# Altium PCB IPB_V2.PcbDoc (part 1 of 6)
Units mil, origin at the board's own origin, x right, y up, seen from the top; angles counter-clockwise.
Board outline 14000 x 12000 mil, 6 copper layers (Top, L2 - Plane/Horiz, L3 - Horiz, L4 - Vert, L5 - Plane/Horiz, Bottom), stack 61.468 mil thick; 657 components, 436 nets, 1897 pads, 873 vias.
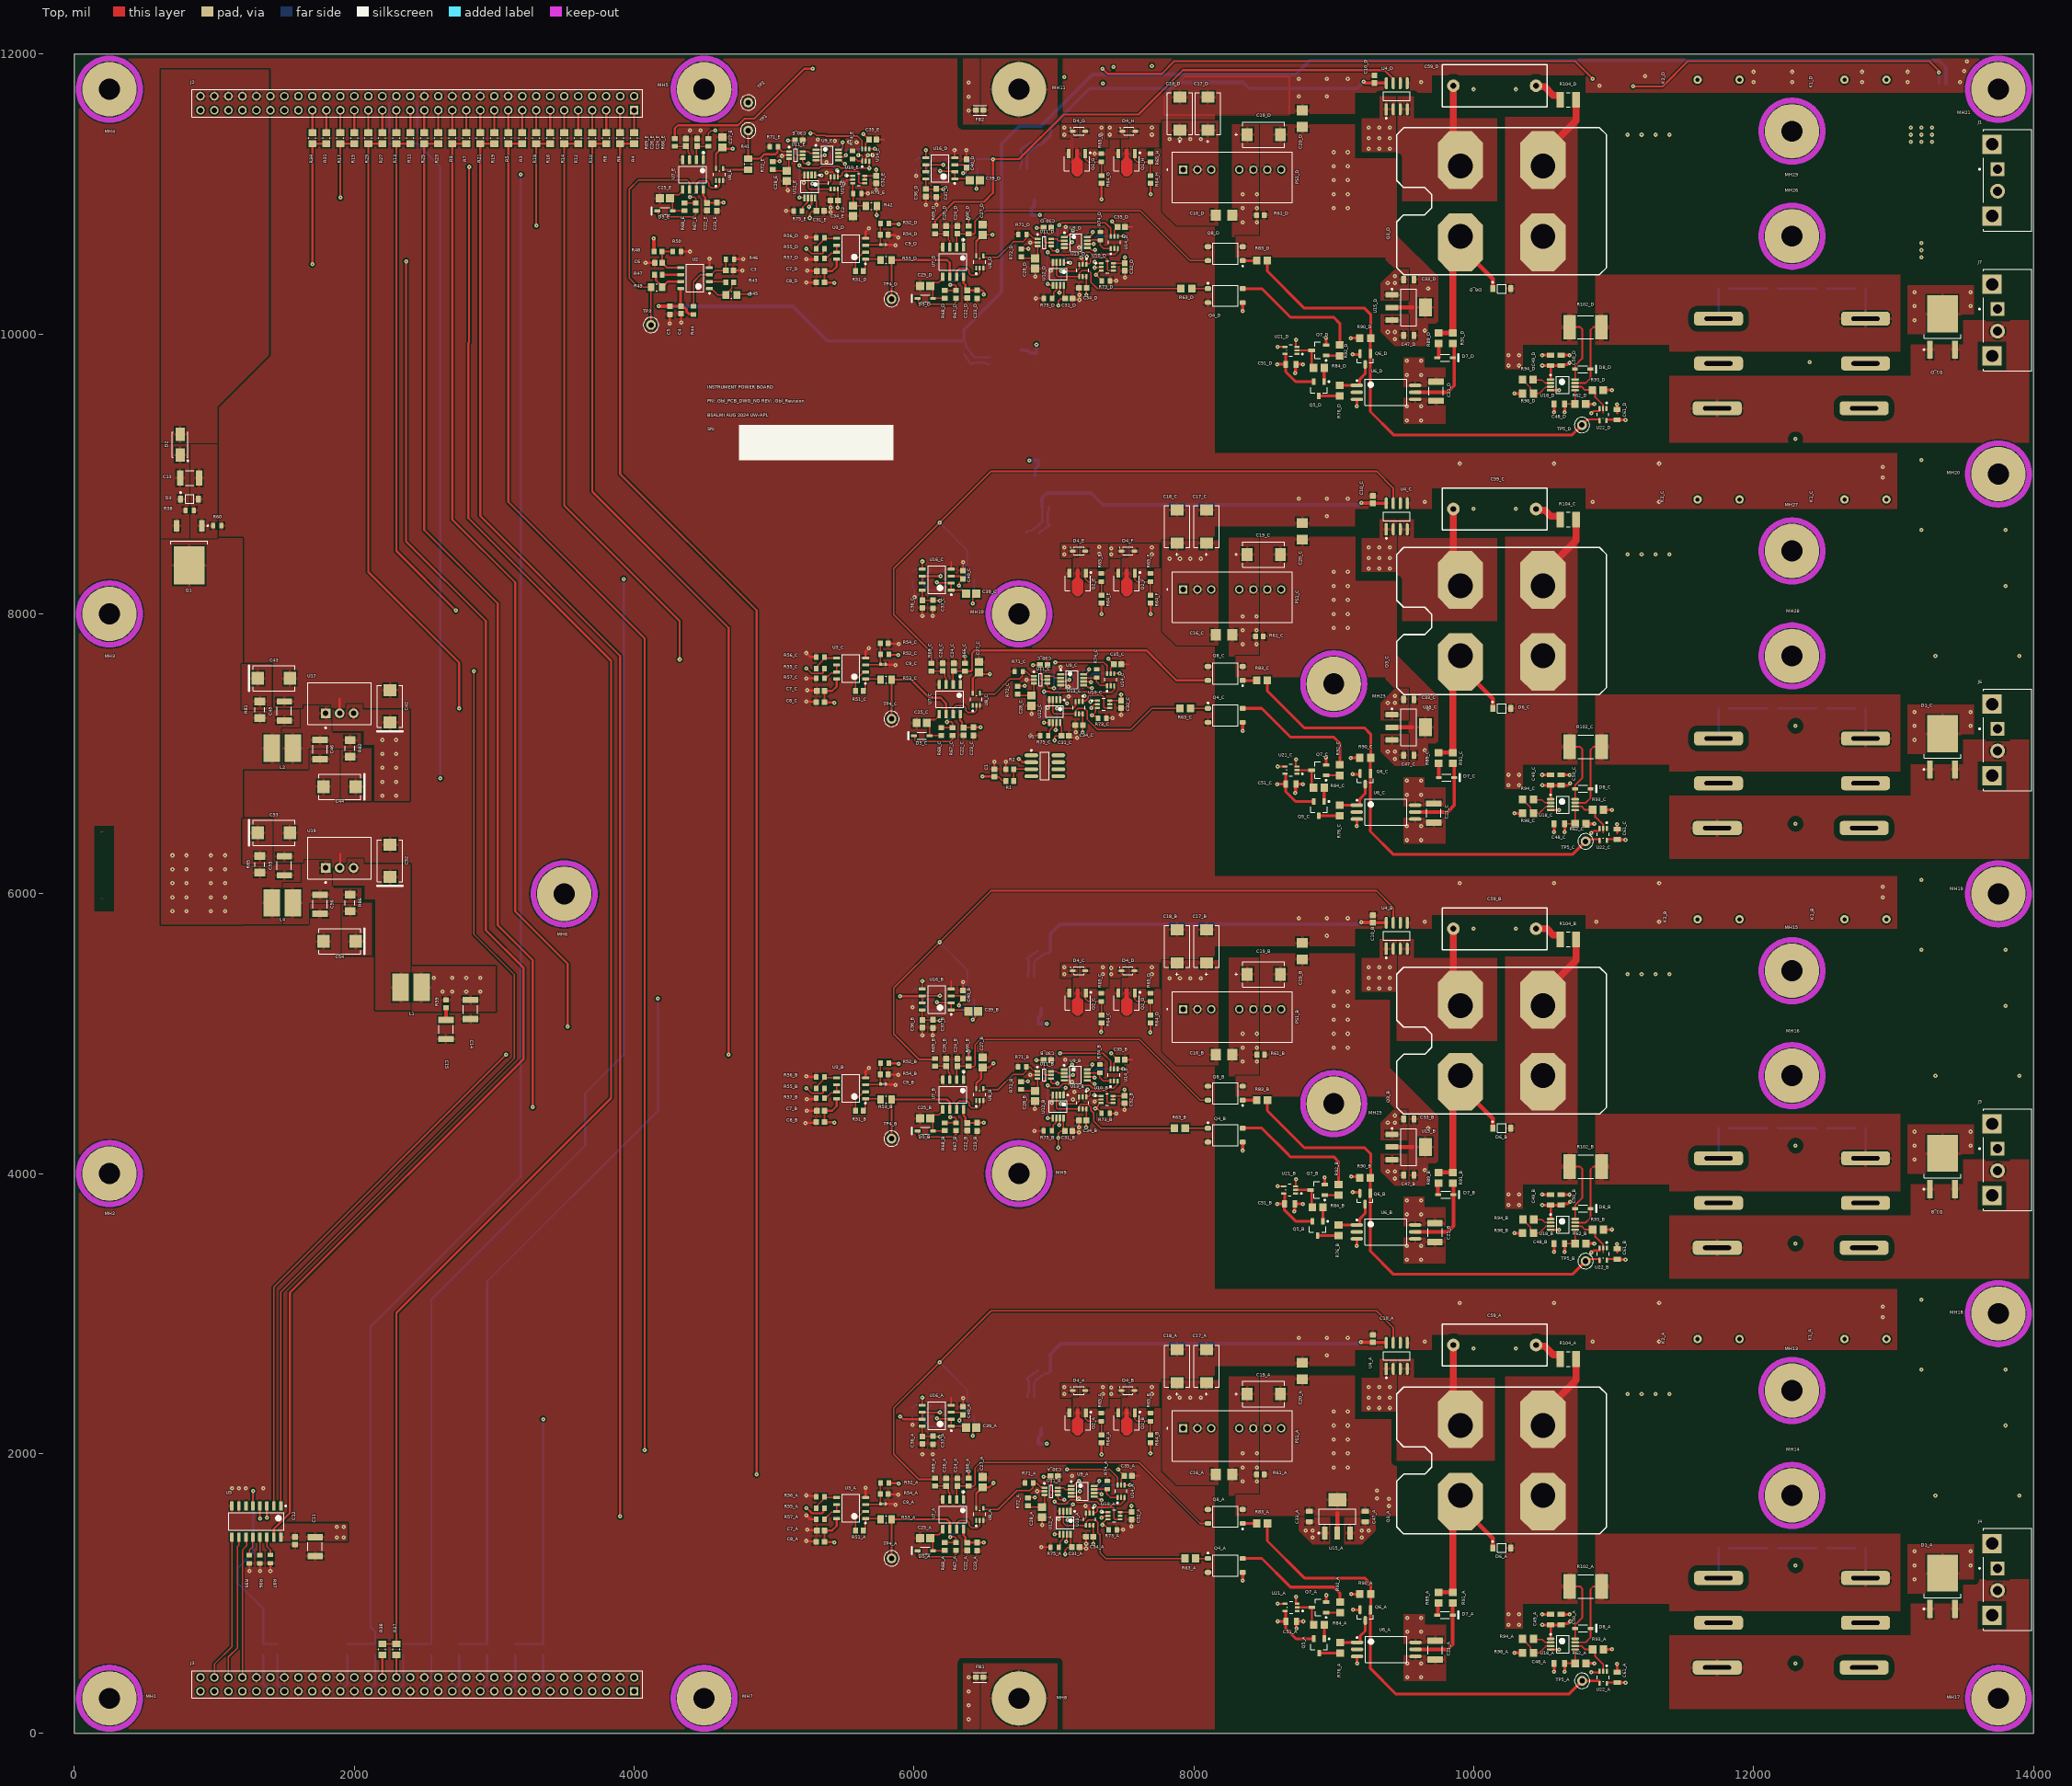
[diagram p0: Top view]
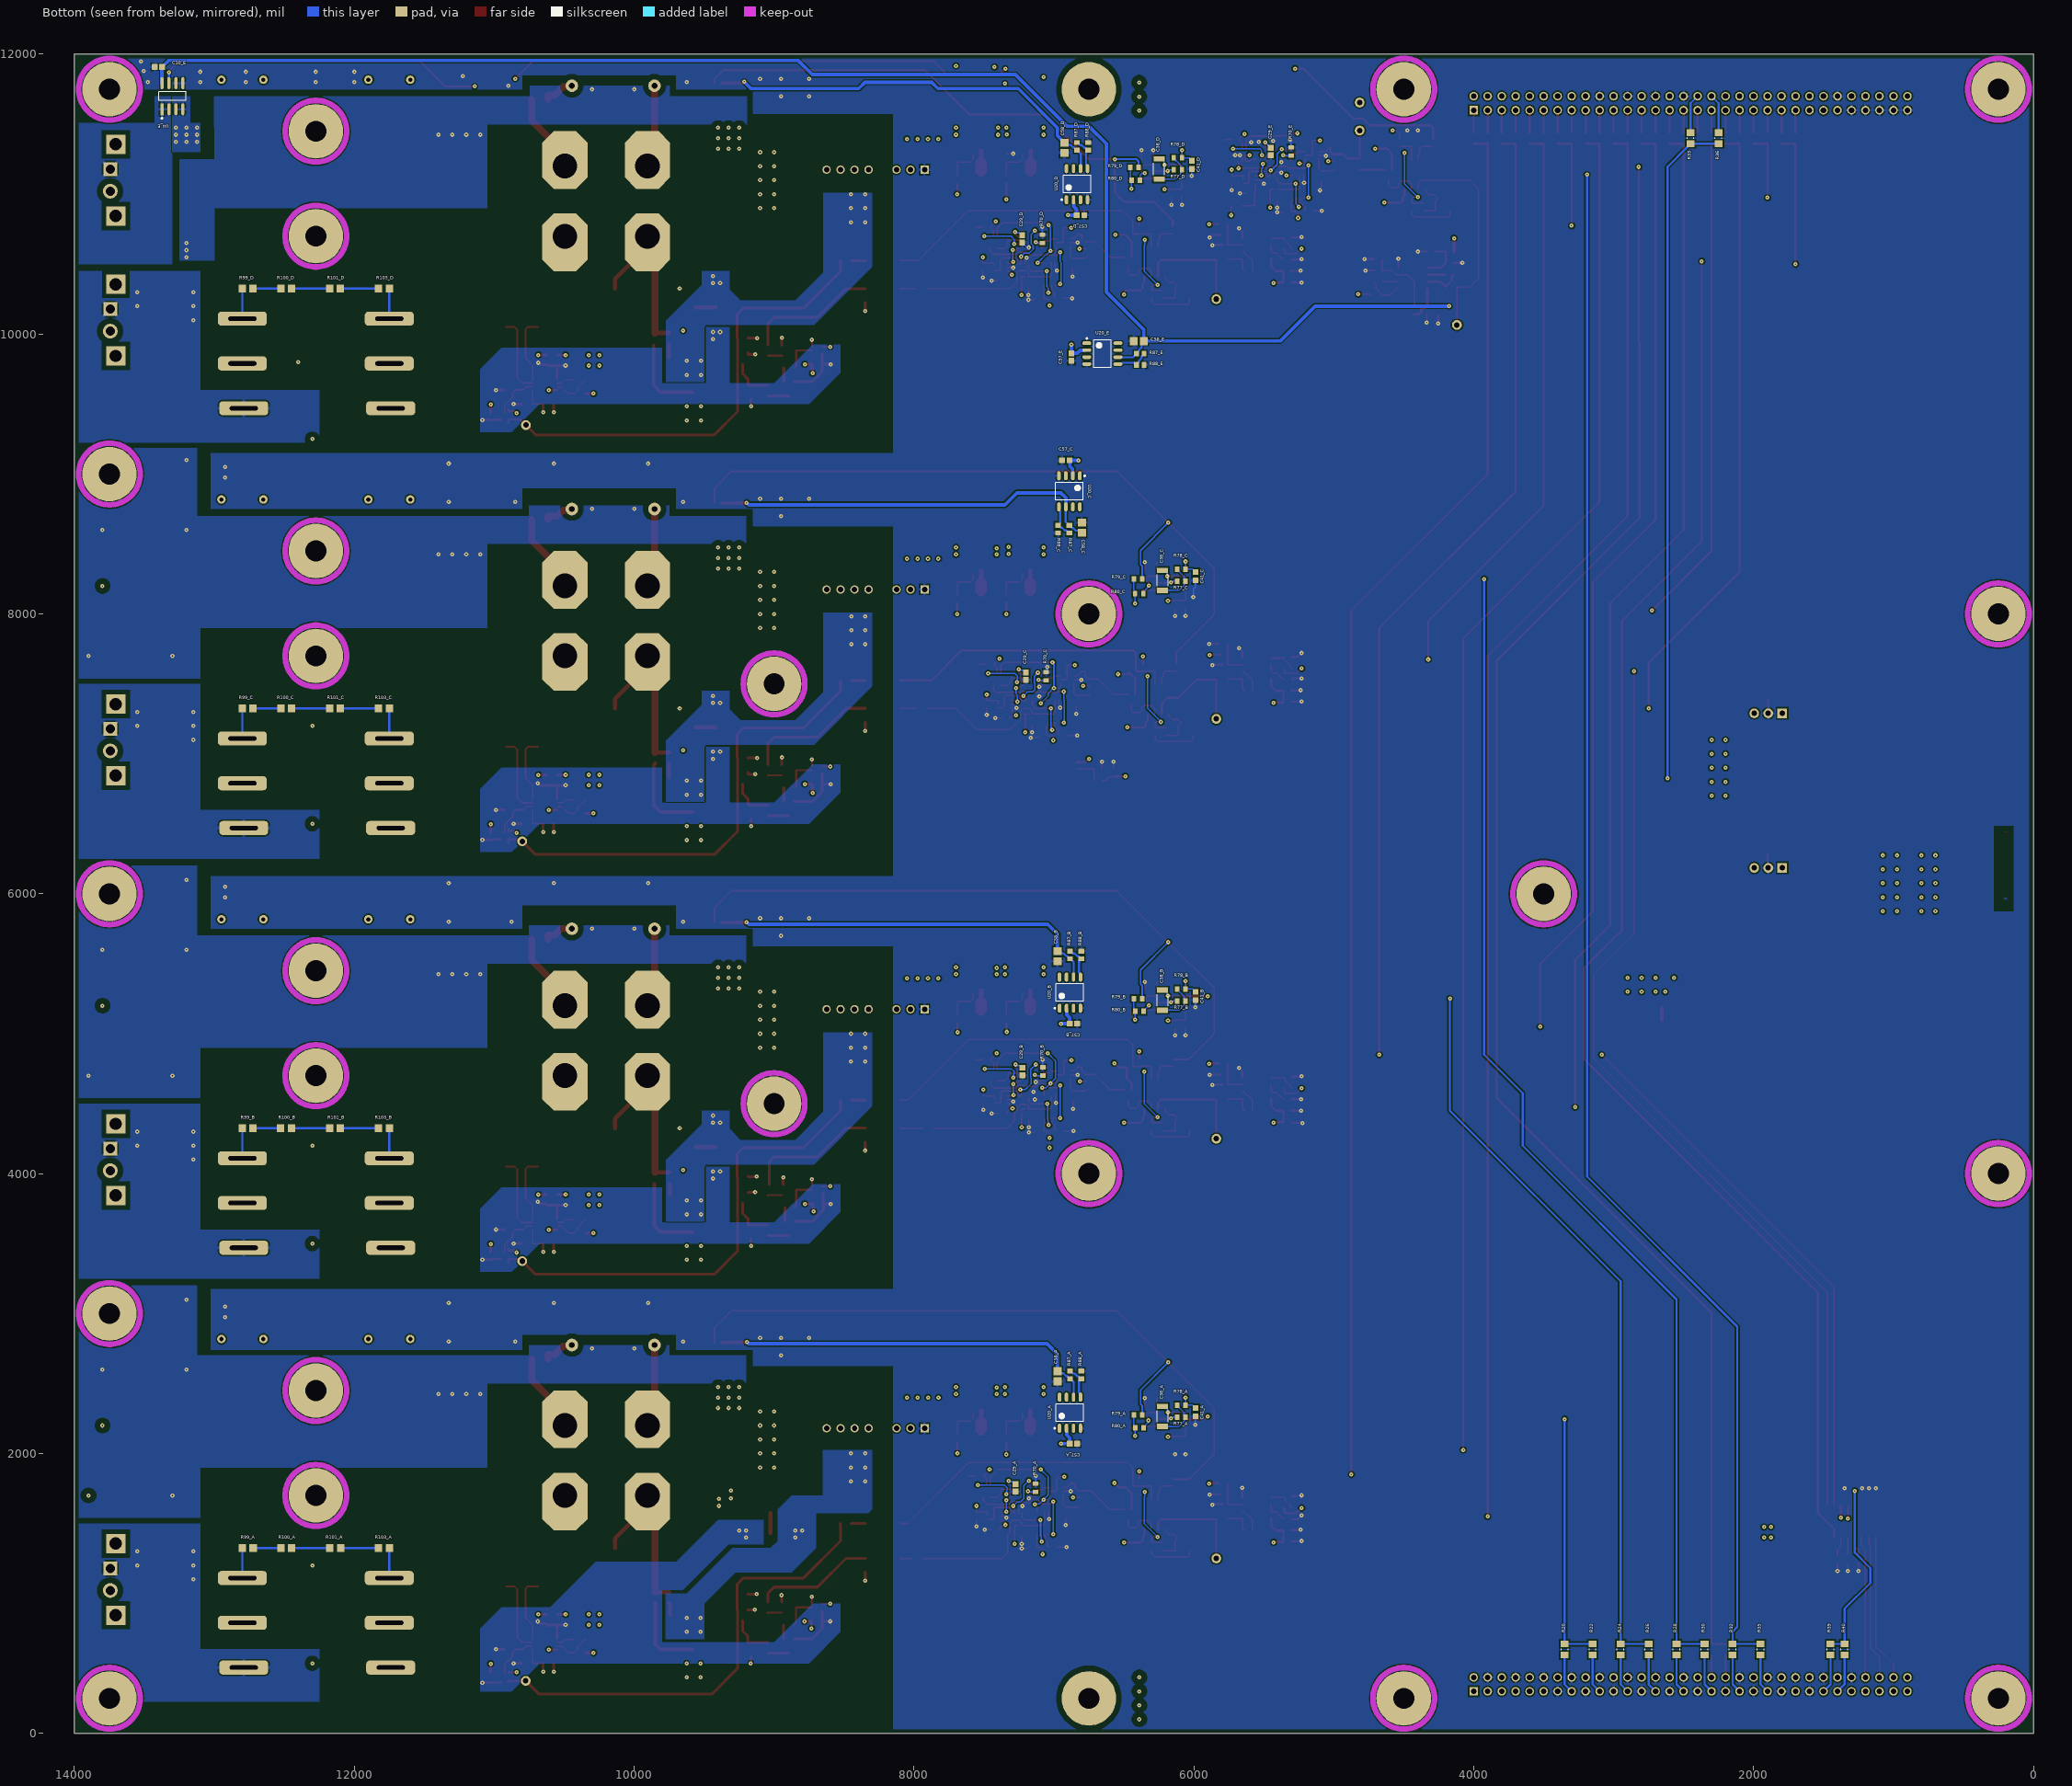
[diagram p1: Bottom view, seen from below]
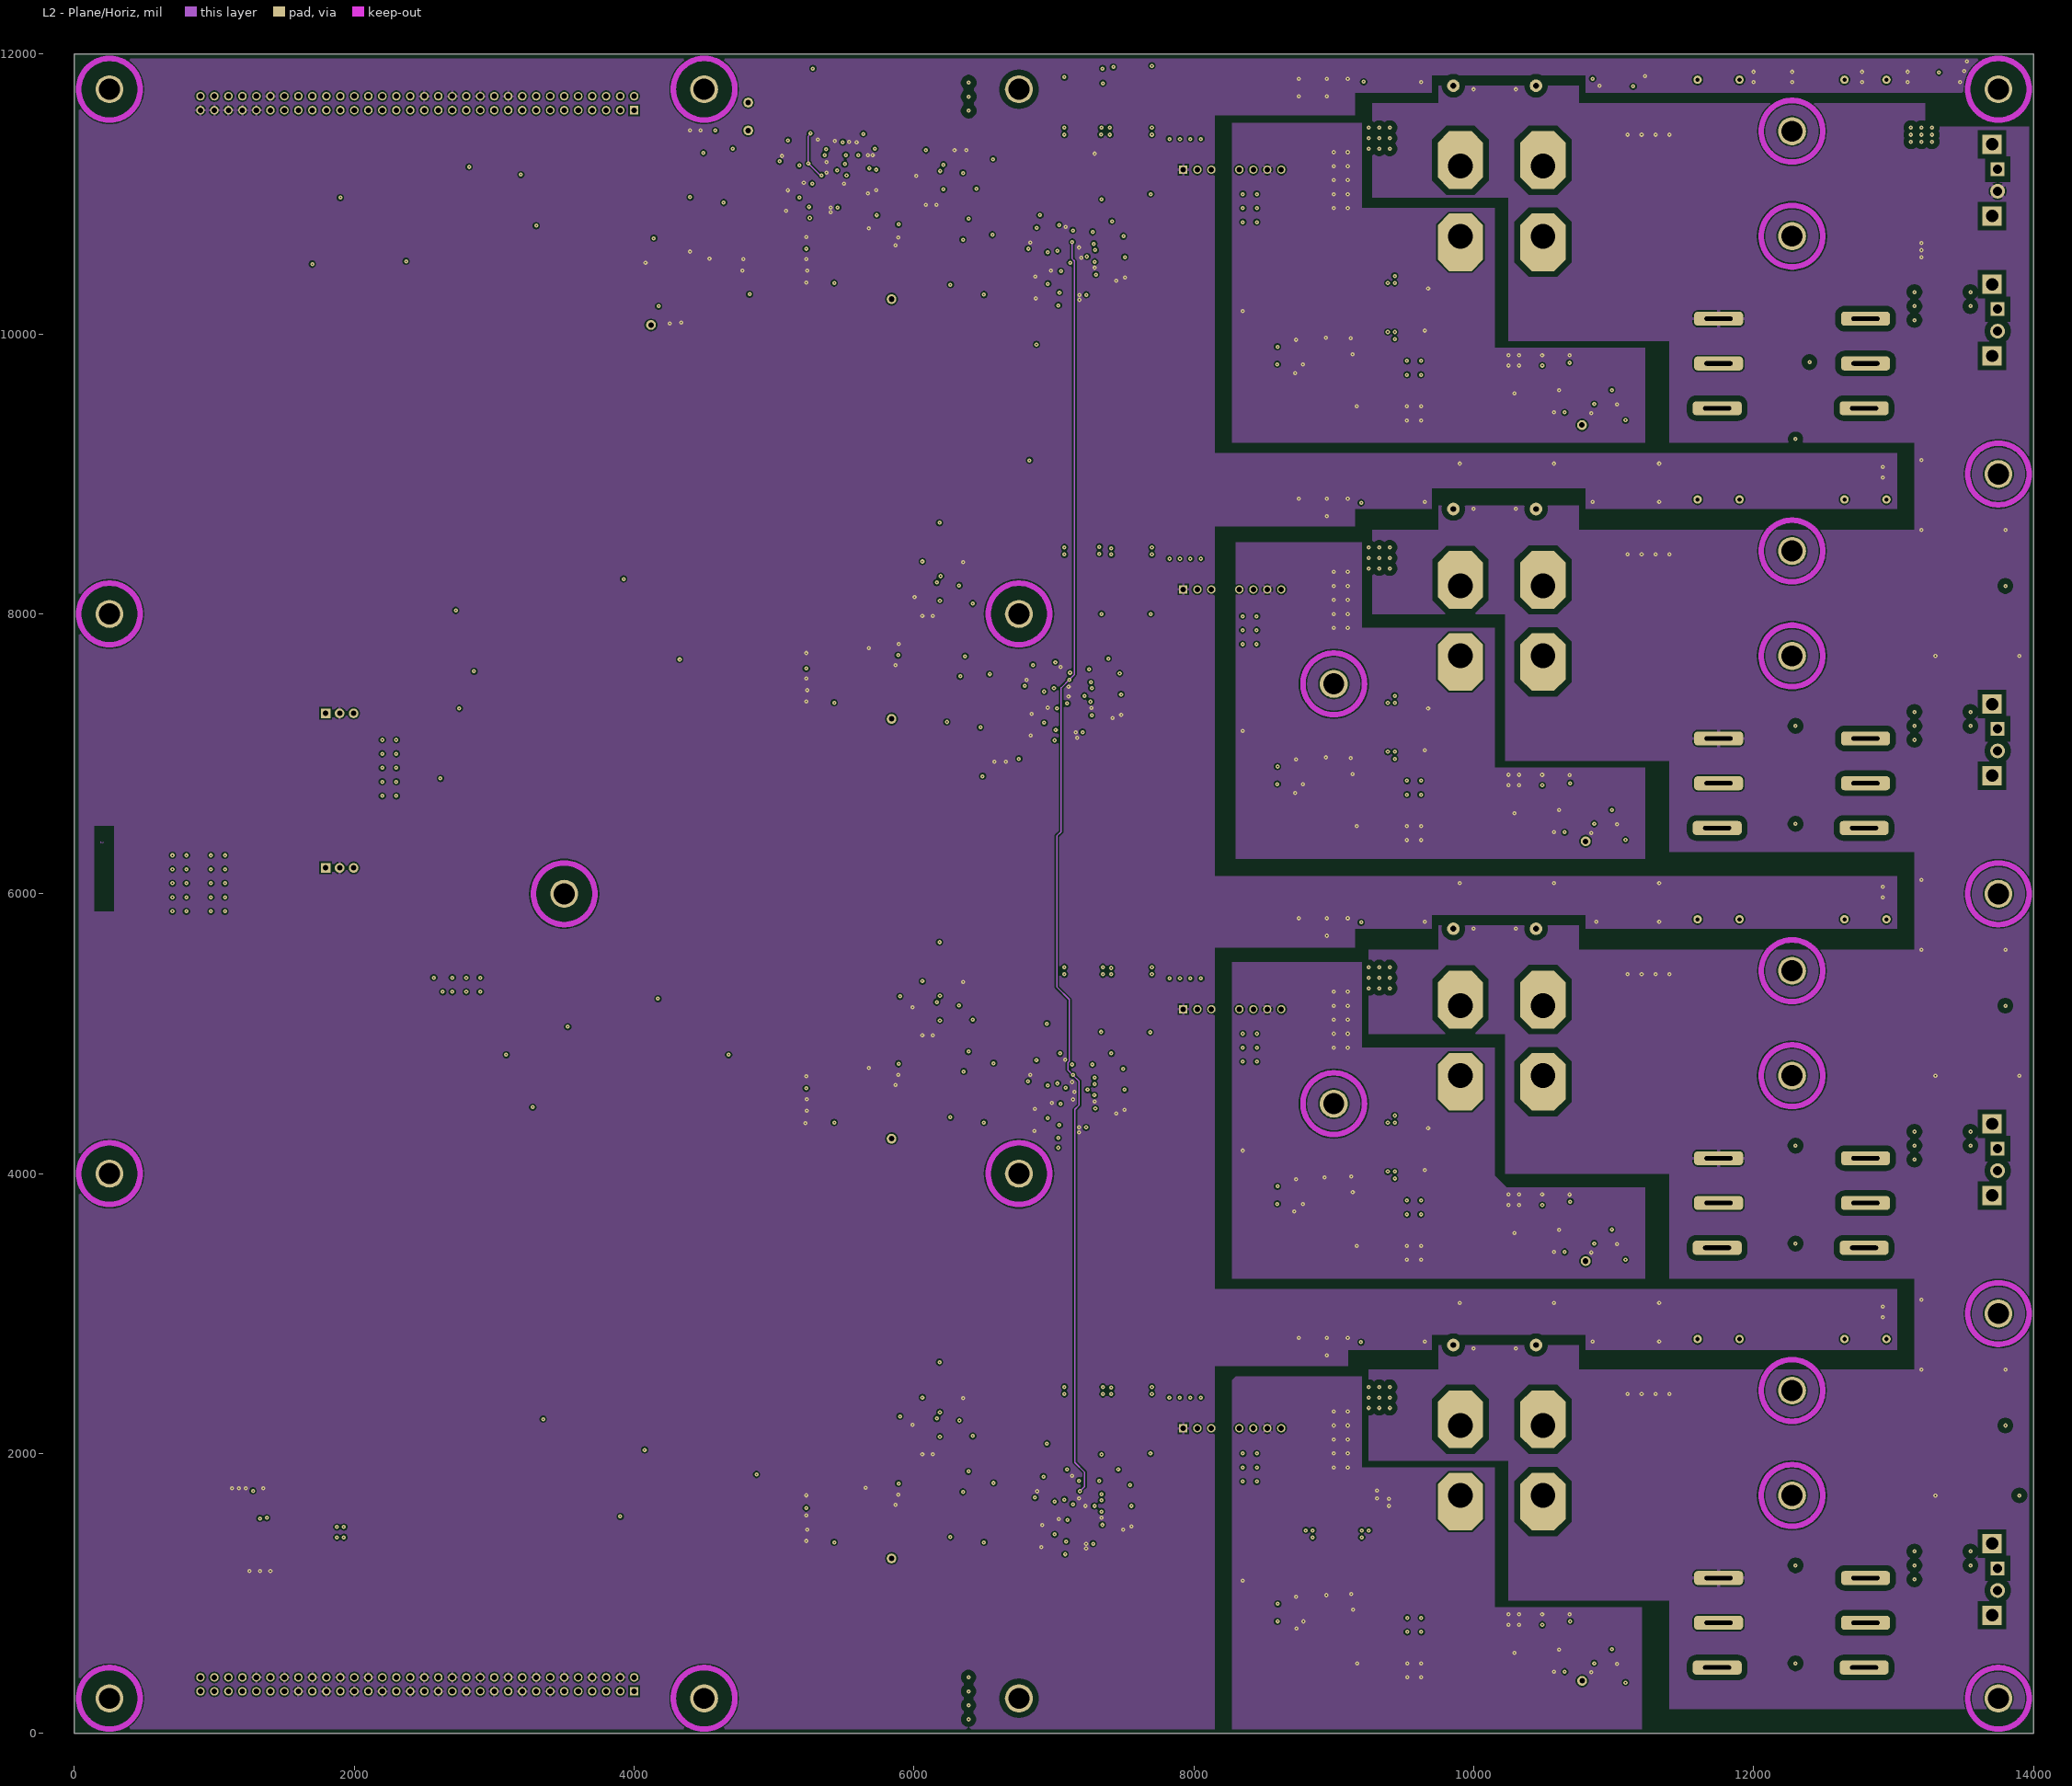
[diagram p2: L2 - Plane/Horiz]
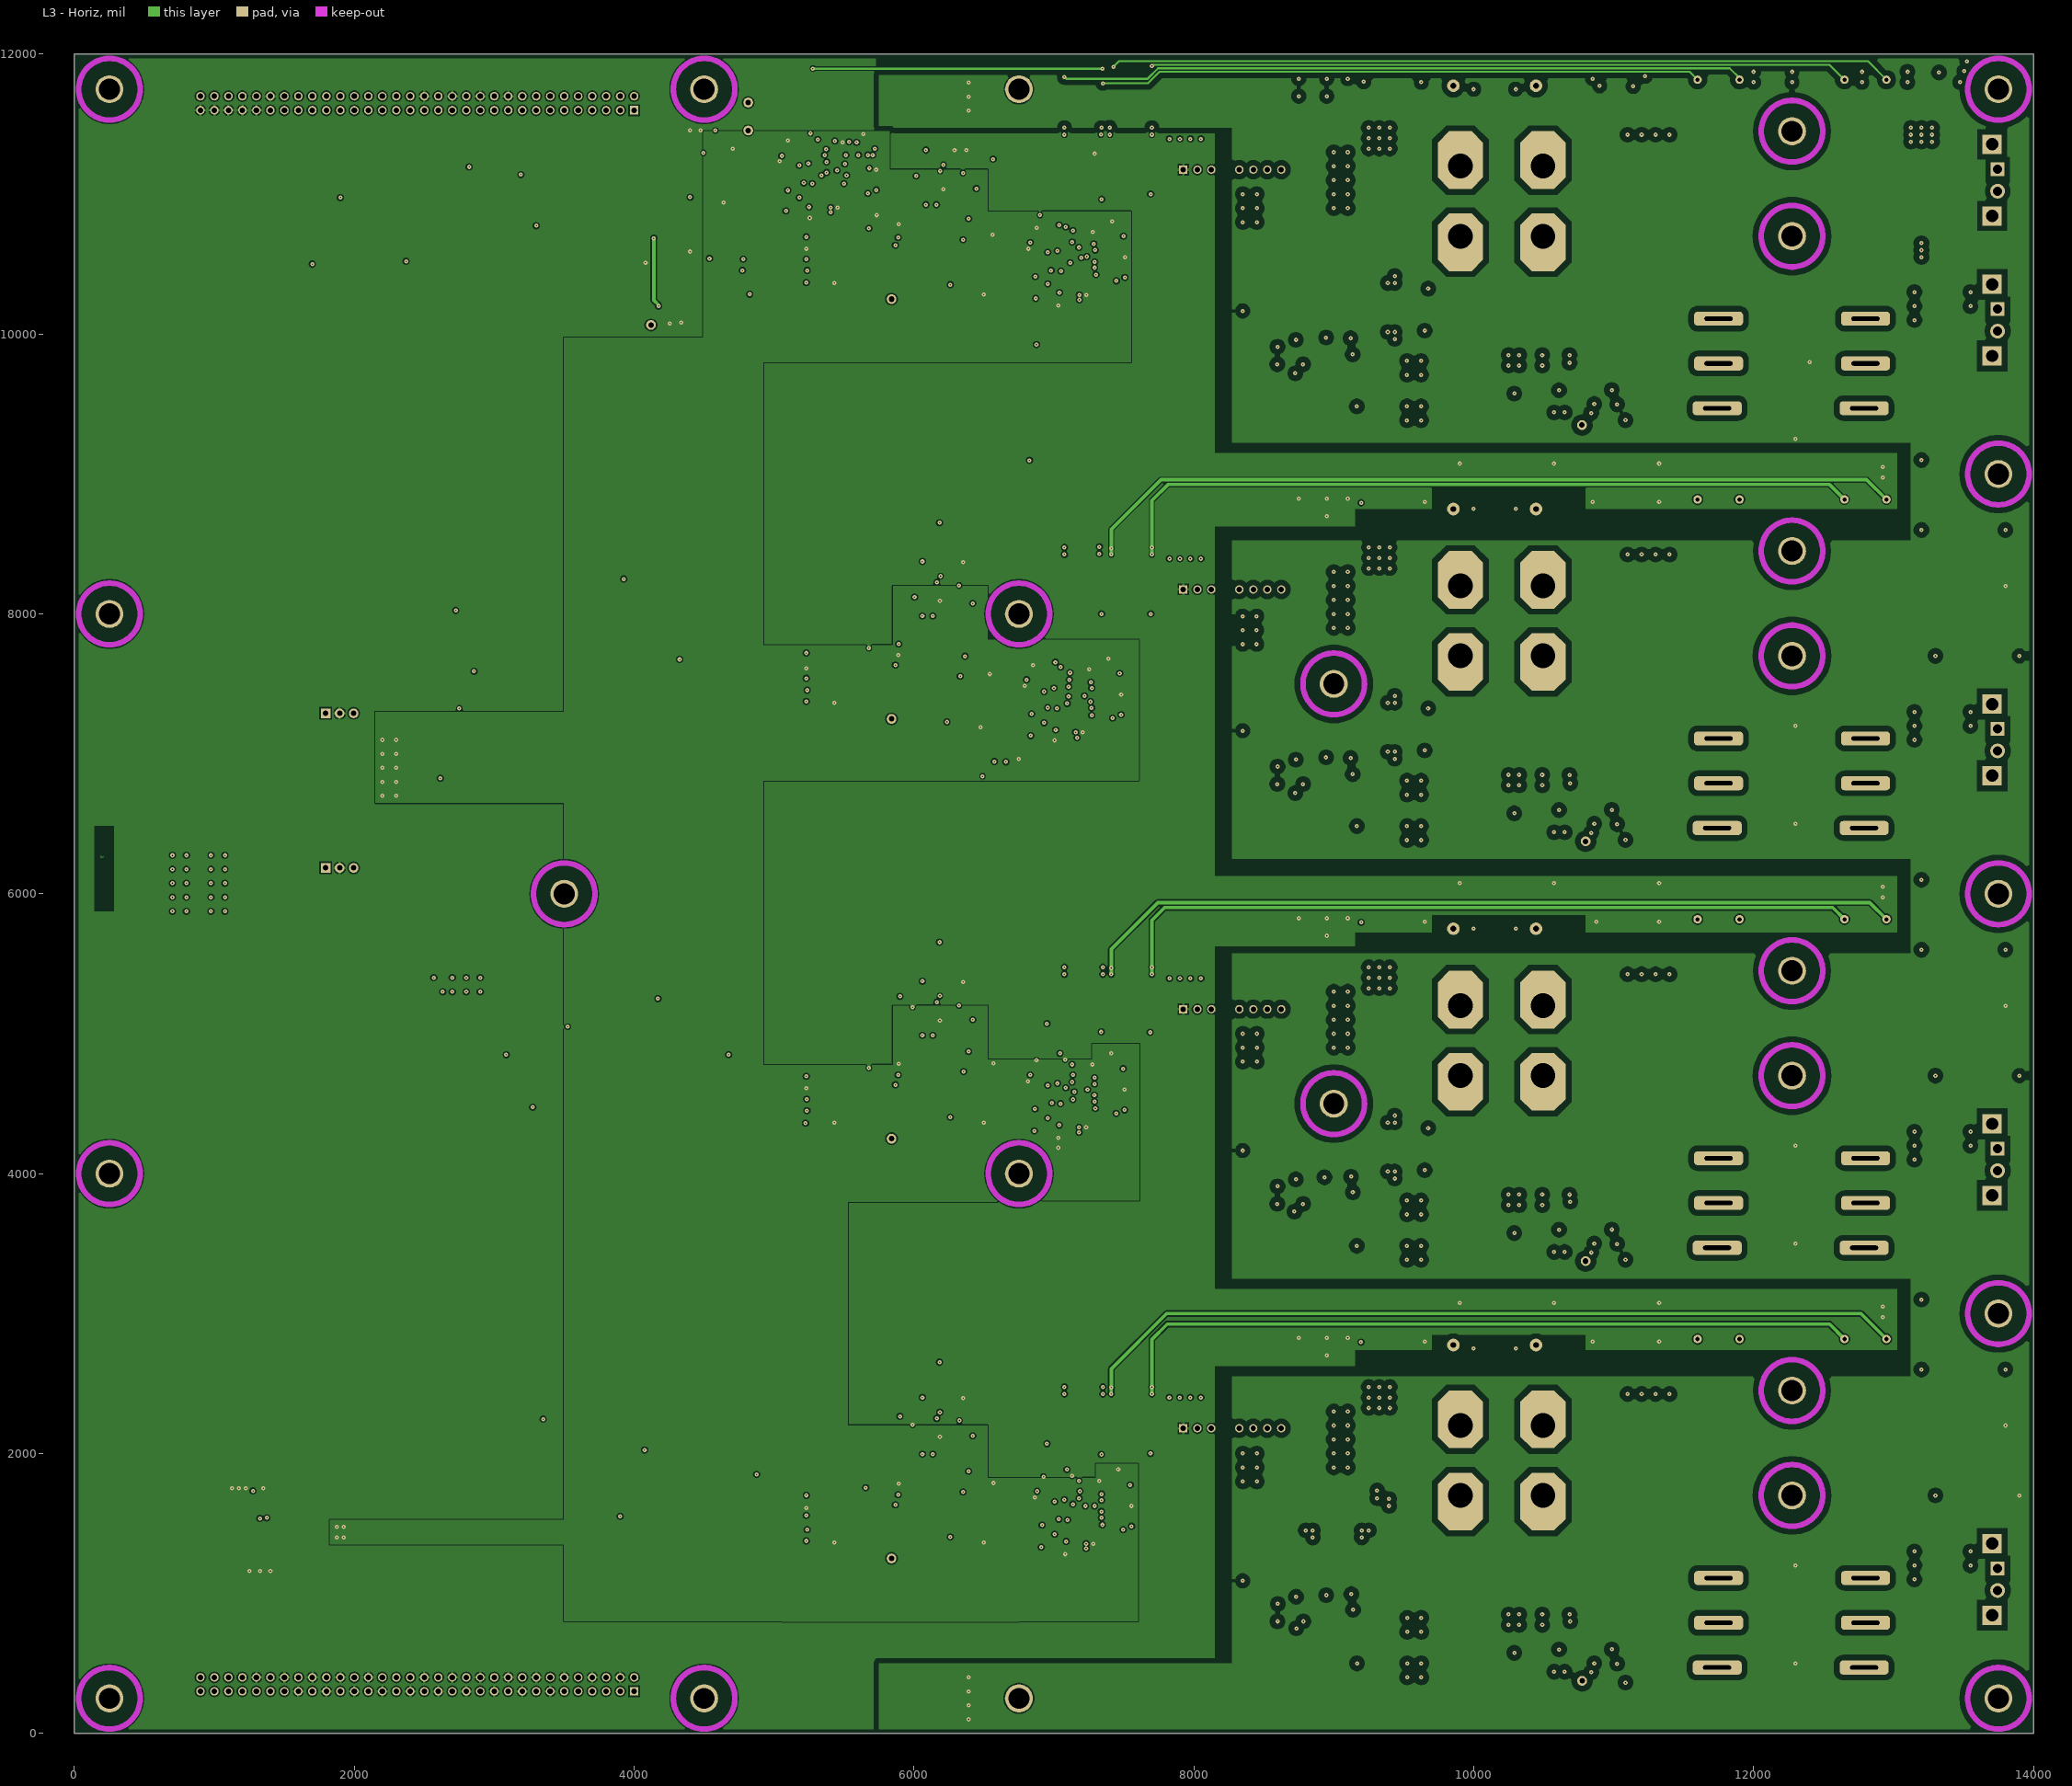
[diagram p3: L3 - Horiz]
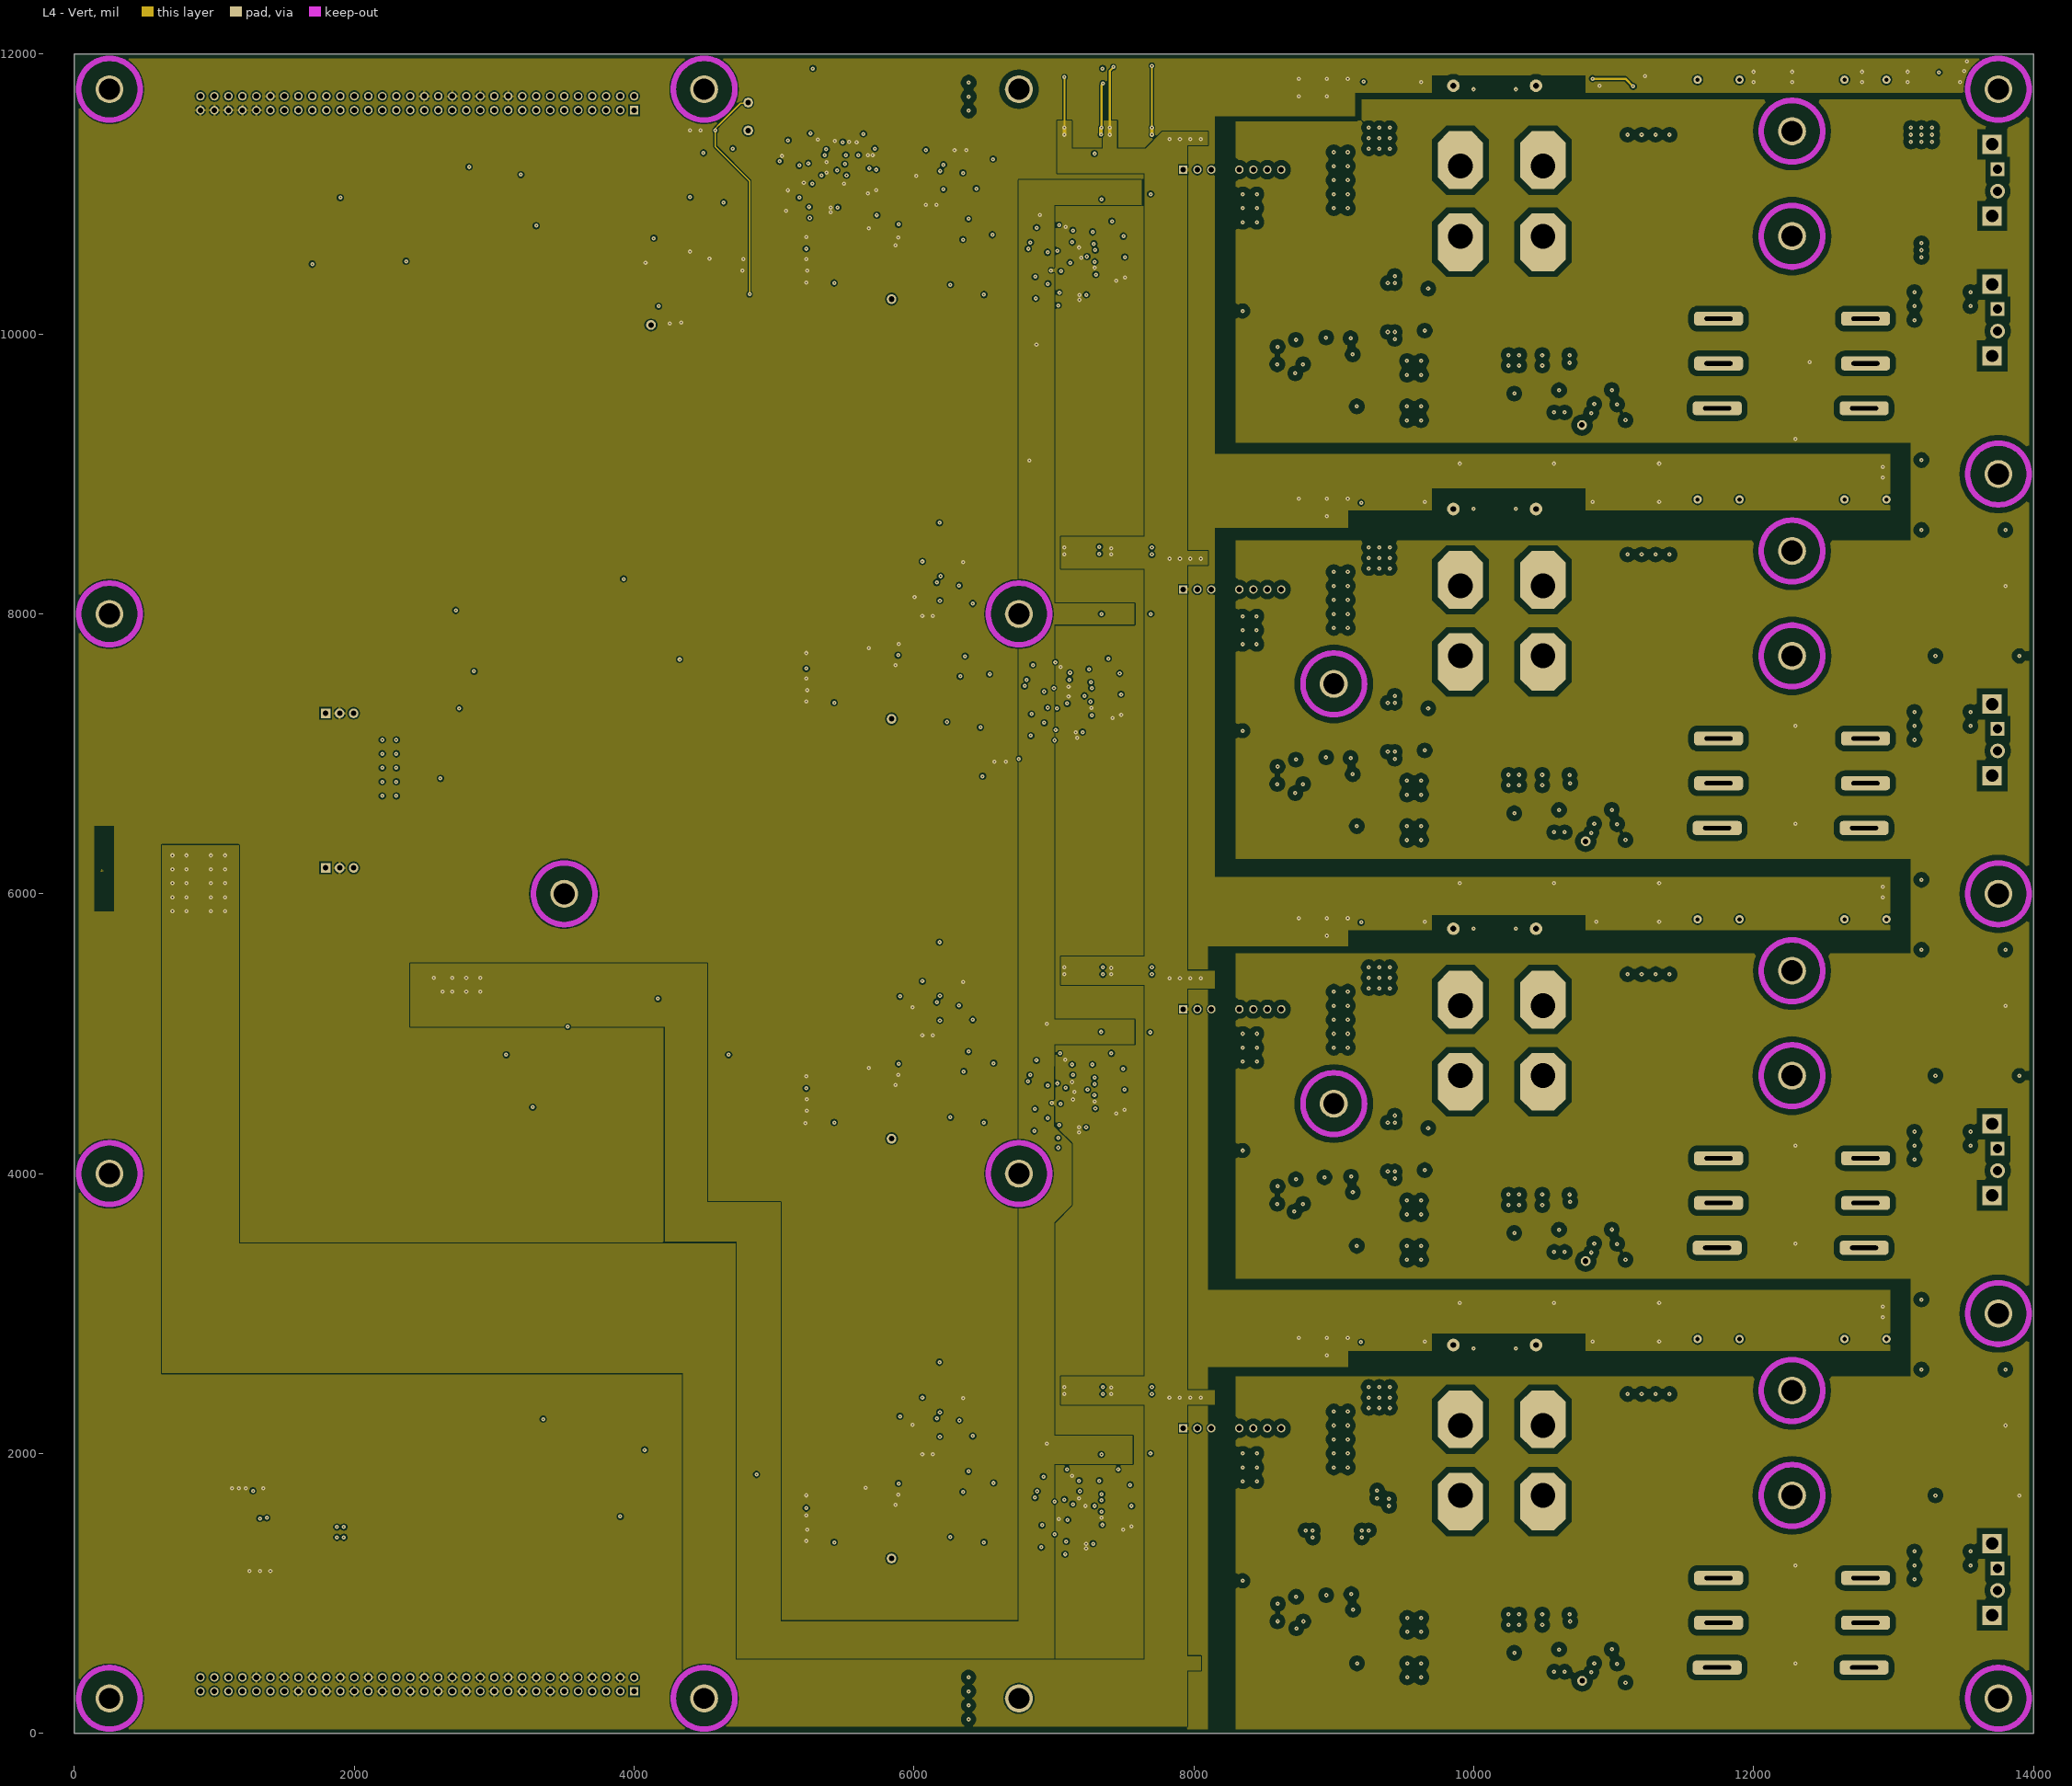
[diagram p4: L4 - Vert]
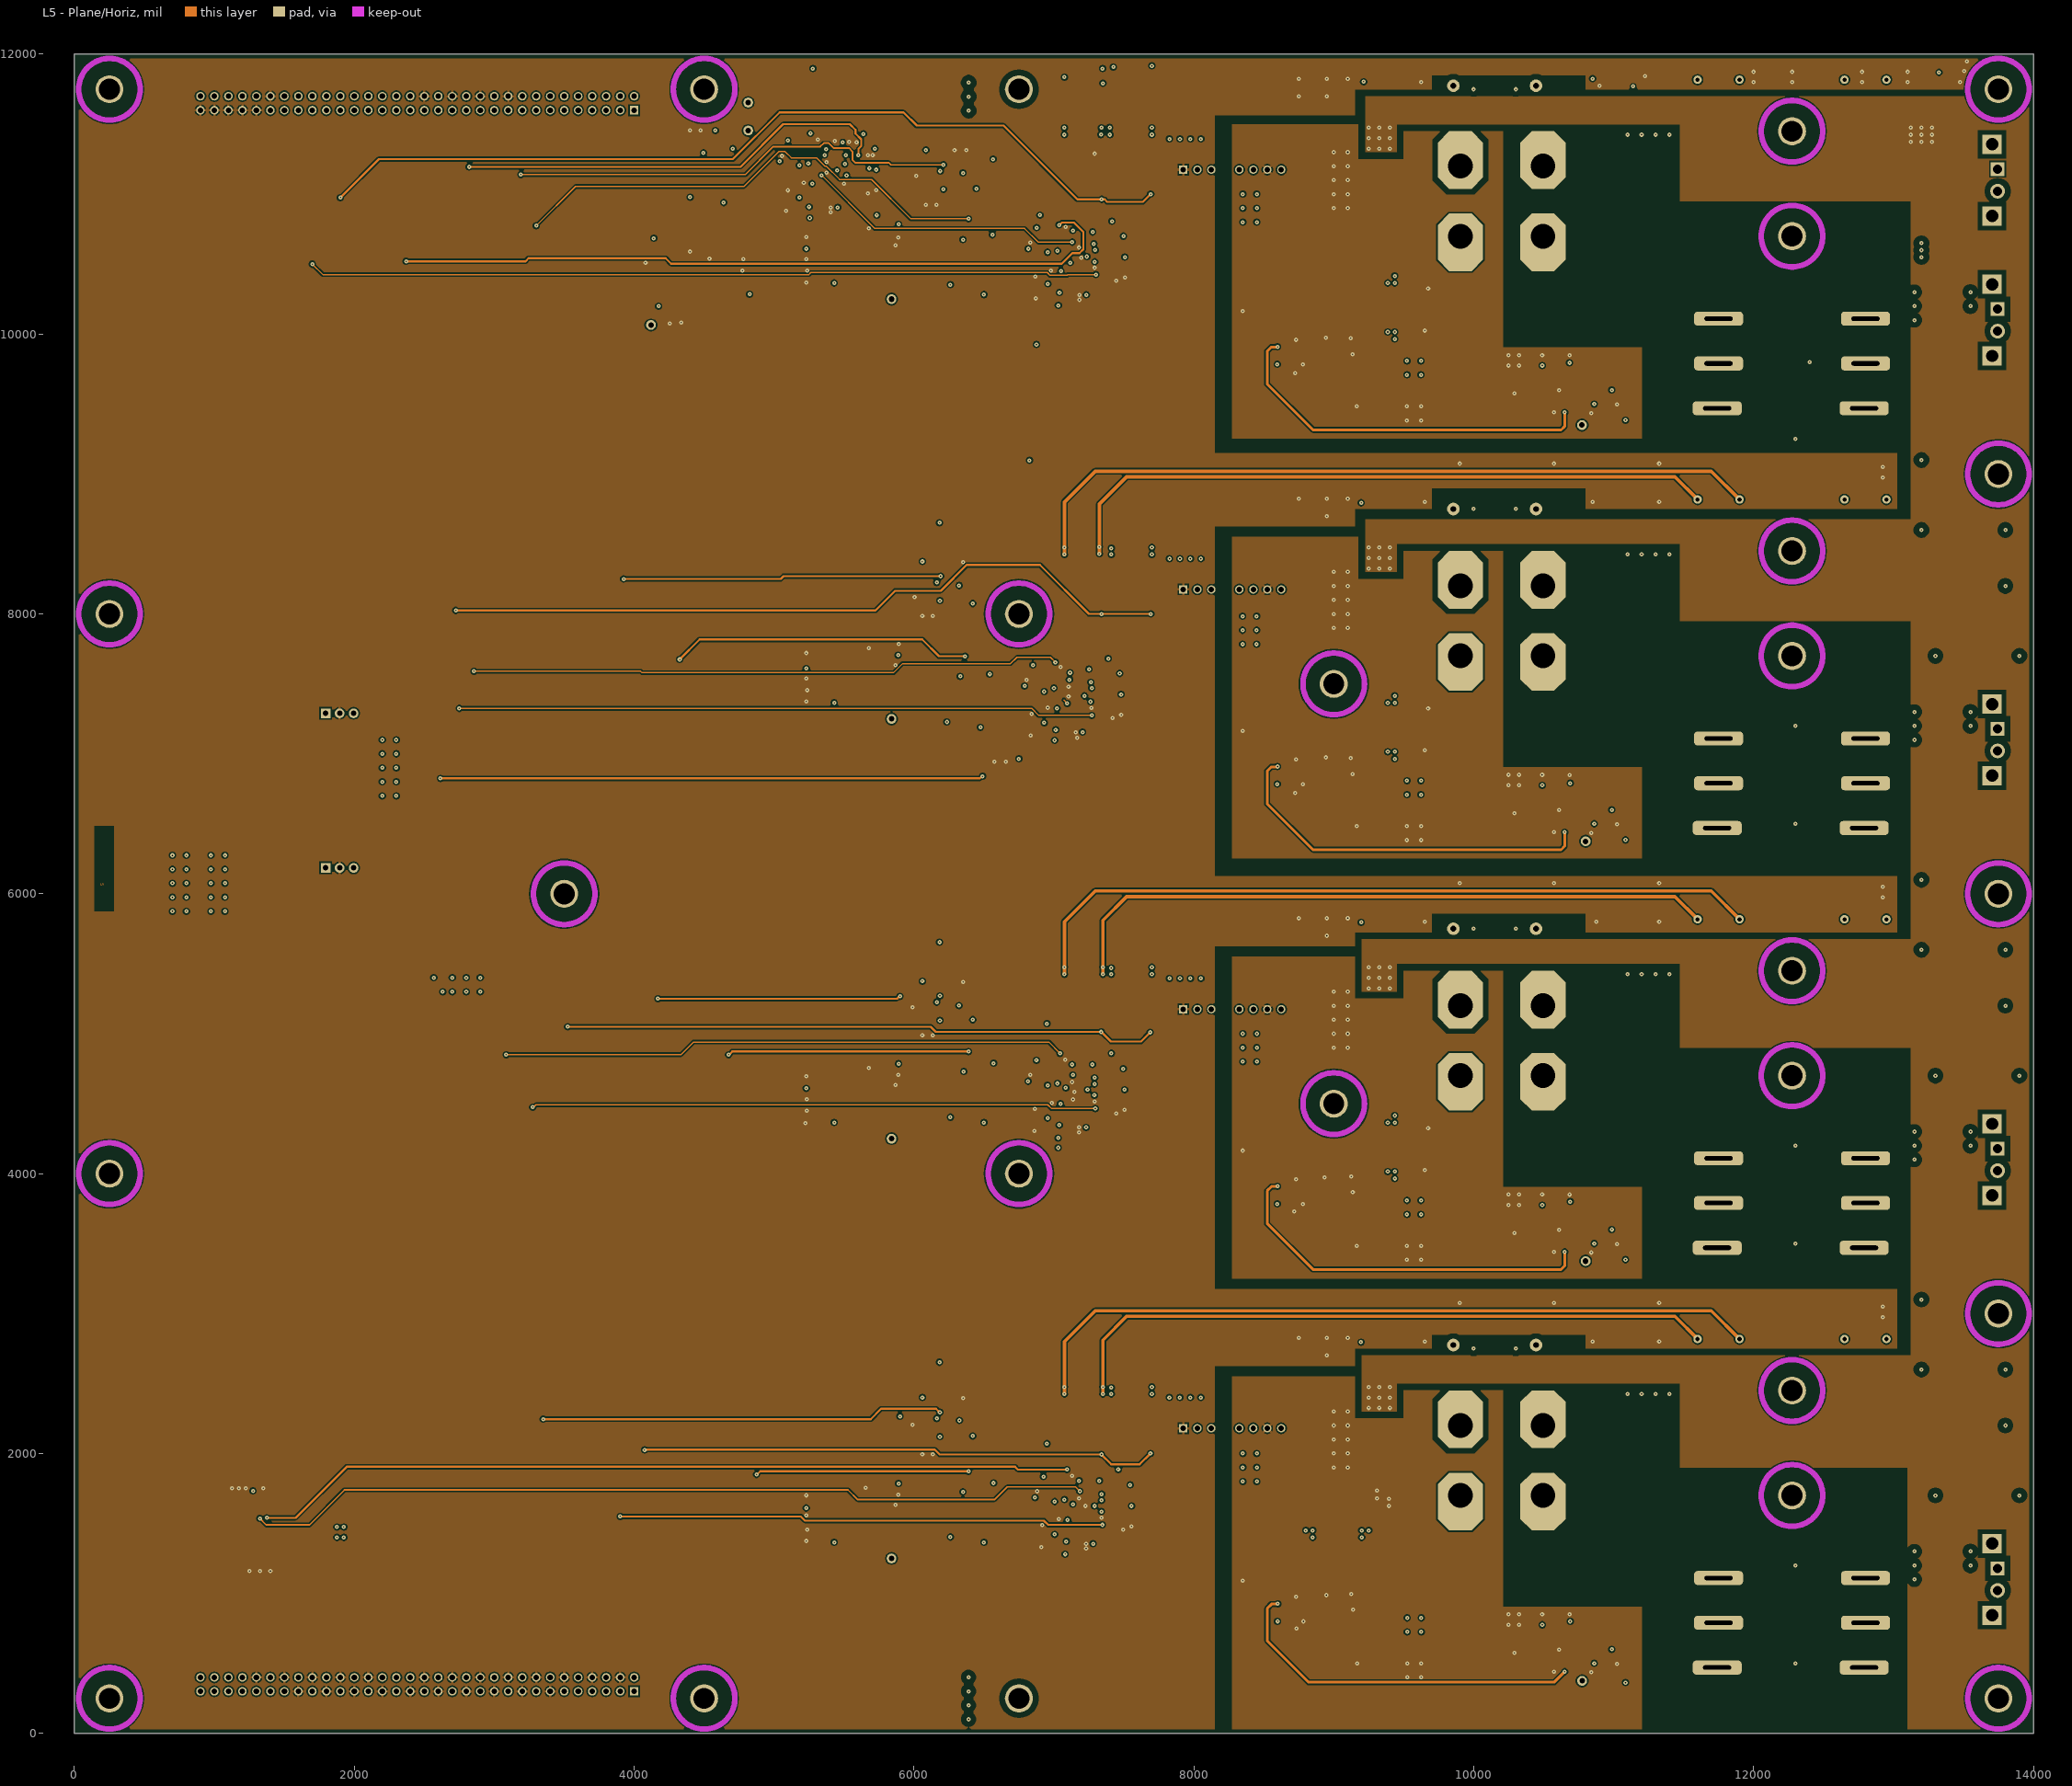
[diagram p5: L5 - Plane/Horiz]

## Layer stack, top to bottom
Top Solder: solder mask 0.4, Solder Resist, Dk 3.5
Top: signal copper 1.378
Dielectric 2: prepreg 4.2, PP-013, Dk 4.3
Dielectric 3: prepreg 4.2, PP-013, Dk 4.3
L2 - Plane/Horiz: signal copper 1.378
Dielectric 4: core 14, PP-013, Dk 4.3
L3 - Horiz: signal copper 1.378
Dielectric 5: prepreg 4.2, PP-013, Dk 4.3
Dielectric 6: prepreg 4.2, PP-013, Dk 4.3
L4 - Vert: signal copper 1.378
Dielectric 7: core 14, PP-013, Dk 4.3
L5 - Plane/Horiz: signal copper 1.378
Dielectric 8: prepreg 4.2, PP-013, Dk 4.3
Dielectric 9: prepreg 4.2, PP-013, Dk 4.3
Bottom: signal copper 1.378
Bottom Solder: solder mask 0.4, Solder Resist, Dk 3.5

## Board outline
14000,0 14000,12000 0,12000 0,0

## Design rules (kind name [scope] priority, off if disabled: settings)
BoardOutlineClearance [All] p1: gap=30 ignorepadtopadclearanceinfootprint=FALSE
BoardOutlineClearance BoardOutlineClearance_L2 [OnLayer('Layer 2')] p2 off: gap=15 ignorepadtopadclearanceinfootprint=FALSE
BoardOutlineClearance BoardOutlineClearance_L3 [OnLayer('Layer 3')] p3 off: gap=15 ignorepadtopadclearanceinfootprint=FALSE
BoardOutlineClearance BoardOutlineClearance_L4 [OnLayer('Layer 4')] p4 off: gap=15 ignorepadtopadclearanceinfootprint=FALSE
BoardOutlineClearance BoardOutlineClearance_L5 [OnLayer('Layer 5')] p5 off: gap=15 ignorepadtopadclearanceinfootprint=FALSE
BoardOutlineClearance BoardOutlineClearance_TOP [OnLayer('Top Layer')] p6 off: gap=10 ignorepadtopadclearanceinfootprint=FALSE
BoardOutlineClearance BoardOutlineClearance_BOTTOM [OnLayer('Bottom Layer')] p7 off: gap=10 ignorepadtopadclearanceinfootprint=FALSE
Clearance Clearance_CGND [InNet('CGND') vs Not(InNet('NetFB2_2') Or InNet('NetFB1_2'))] p1: gap=40 ignorepadtopadclearanceinfootprint=TRUE
Clearance Clearance_NETFB1 [InNet('LV_GND') vs InNet('NetFB2_2') Or InNet('NetFB1_2')] p2: gap=40 ignorepadtopadclearanceinfootprint=TRUE
Clearance Clearance_Mounting-Hole-HV [InNetClass('Mounting Hole') vs (InNetClass('MOSFET INPUT') OR InNetClass('MOSFET OUTPUT') OR InNetClass('N187_REF') OR InNetClass('P187_REF') OR InNetClass('POSITIVE HIGHSIDE') OR InNetClass('RELAY INPUT') OR InNetClass('RELAY OUTPUT'))] p3: gap=31 ignorepadtopadclearanceinfootprint=TRUE
Clearance Clearance_Mounting-Hole-2 [InComponentClass('MH')] p4: gap=40 ignorepadtopadclearanceinfootprint=TRUE
Clearance Clearance_LV-HV-Separation [InNetClass('P187_REF')   OR InNetClass('N187_REF') vs InNetClass('LV_NETCLASS')] p5: gap=40 ignorepadtopadclearanceinfootprint=FALSE
Clearance Clearance_P187-Netclass [InNetClass('P187_REF') vs InNetClass('N187_REF')] p6: gap=40 ignorepadtopadclearanceinfootprint=FALSE
Clearance Clearance_P187-HIGHSIDE [InNetClass('POSITIVE HIGHSIDE') vs InNetClass('RELAY OUTPUT')] p7: gap=40 ignorepadtopadclearanceinfootprint=FALSE
Clearance Clearance_P187-HIGHSIDE_RELAYIN [InNetClass('POSITIVE HIGHSIDE') vs InNetClass('RELAY INPUT')] p8: gap=40 ignorepadtopadclearanceinfootprint=FALSE
Clearance Clearance_N187-Netclass [InNetClass('N187_REF') vs InNetClass('P187_REF')] p9: gap=40 ignorepadtopadclearanceinfootprint=FALSE
Clearance Clearance_MOSFET-Separation [InNetClass('MOSFET INPUT') vs InNetClass('MOSFET OUTPUT')] p10: gap=40 ignorepadtopadclearanceinfootprint=FALSE
Clearance Clearance_RELAY-Separation [InNetClass('RELAY INPUT') vs InNetClass('RELAY OUTPUT')] p11: gap=40 ignorepadtopadclearanceinfootprint=FALSE
Clearance Clearance_1 [All] p12: gap=10 ignorepadtopadclearanceinfootprint=FALSE except(6: Arc-Arc Arc-Track Arc-SMDPad Track-Track Track-SMDPad SMDPad-SMDPad)
ComponentClearance [All] p1: gap=5 collisioncheckmode=3 verticalgap=10 showdistances=FALSE
Creepage Creepage_CGND [InNet('CGND')] p1 off: checkdistance=15 ignoreinternallayers=FALSE applytopolygonpour=TRUE
Creepage Creepage_N187 [InNetClass('N187_REF') vs InNetClass('P187_REF')] p2 off: checkdistance=9.8 ignoreinternallayers=FALSE applytopolygonpour=TRUE
Creepage Creepage_P187 [InNetClass('P187_REF') vs InNetClass('N187_REF')] p3 off: checkdistance=9.8 ignoreinternallayers=FALSE applytopolygonpour=TRUE
Creepage Creepage_N187_EXT [InNetClass('N187_REF') vs InNetClass('P187_REF')] p4 off: checkdistance=32 applytopolygonpour=TRUE
Creepage Creepage_P187_EXT [InNetClass('P187_REF') vs InNetClass('N187_REF')] p5 off: checkdistance=32 applytopolygonpour=TRUE
HoleSize [All] p1: absolutevalues=TRUE maxlimit=300 minlimit=8 maxpercent=80.000 minpercent=20.000
MinimumAnnularRing [All] p1: minimumring=10
MinimumSolderMaskSliver [All] p1: minsoldermaskwidth=0
NetAntennae [All] p1: netantennaetolerance=20
PlaneConnect [All] p1: pad.planeconnectstyle=Relief pad.reliefexpansion=20 pad.reliefentries=4 pad.reliefconductorwidth=20 pad.reliefairgap=10 via.planeconnectstyle=Direct via.reliefexpansion=20 via.reliefentries=4 via.reliefconductorwidth=20 via.reliefairgap=10
PolygonConnect [All] p1: thpad.connectstyle=Relief thpad.reliefconductorwidth=20 thpad.reliefentries=4 thpad.polygonreliefangle="90 Angle" thpad.airgapwidth=10 smdpad.connectstyle=Relief smdpad.reliefconductorwidth=20 smdpad.reliefentries=4 smdpad.polygonreliefangle="90 Angle" smdpad.airgapwidth=10 via.connectstyle=Direct via.reliefconductorwidth=20 via.reliefentries=4 via.polygonreliefangle="90 Angle" via.airgapwidth=10
RoutingVias [All] p1: holewidth=15 width=29 viastyle="Through Hole" minholewidth=10 minwidth=29 maxholewidth=28 maxwidth=50
SilkToSilkClearance [All] p1: silktosilkclearance=5
SilkToSolderMaskClearance [IsPad] p1: minsilkscreentomaskgap=3 clearancetoexposedcopper=TRUE
SolderMaskExpansion [All] p1: expansion=4 istentingtop=FALSE
SupplyNets "Schematic Supply Nets_25" [InNet('HV_P12V_D')] p1: voltage=0.000
SupplyNets "Schematic Supply Nets_24" [InNet('HV_P5V_C')] p2: voltage=0.000
SupplyNets "Schematic Supply Nets_21" [InNet('HV_P12V_B')] p3: voltage=0.000
SupplyNets "Schematic Supply Nets_20" [InNet('ISO_RTN_D')] p4: voltage=0.000
SupplyNets "Schematic Supply Nets_18" [InNet('HV_P5V_D')] p5: voltage=0.000
SupplyNets "Schematic Supply Nets_17" [InNet('HV_P5V_B')] p6: voltage=0.000
SupplyNets "Schematic Supply Nets_16" [InNet('HV_P12V_A')] p7: voltage=0.000
SupplyNets "Schematic Supply Nets_15" [InNet('ISO_RTN_C')] p8: voltage=0.000
SupplyNets "Schematic Supply Nets_14" [InNet('N187')] p9: voltage=0.000
SupplyNets "Schematic Supply Nets_13" [InNet('ISO_RTN_B')] p10: voltage=0.000
SupplyNets "Schematic Supply Nets_12" [InNet('ISO_RTN_A')] p11: voltage=0.000
SupplyNets "Schematic Supply Nets_11" [InNet('LV_IGB_P24V')] p12: voltage=0.000
SupplyNets "Schematic Supply Nets_9" [InNet('HV_P5V_A')] p13: voltage=0.000
SupplyNets "Schematic Supply Nets_8" [InNet('HV_P12V_C')] p14: voltage=0.000
SupplyNets "Schematic Supply Nets_7" [InNet('CGND')] p15: voltage=0.000
SupplyNets "Schematic Supply Nets_6" [InNet('LV_ISNS_P5V')] p16: voltage=0.000
SupplyNets "Schematic Supply Nets_4" [InNet('LV_ISNS_P12V')] p17: voltage=0.000
SupplyNets "Schematic Supply Nets_3" [InNet('LV_GND')] p18: voltage=0.000
SupplyNets "Schematic Supply Nets_2" [InNet('COIL_DRV_HIGH_A')] p19: voltage=0.000
SupplyNets "Schematic Supply Nets_1" [InNet('LV_P12V')] p20: voltage=0.000
SupplyNets "Schematic Supply Nets" [InNet('LV_P5V')] p21: voltage=0.000
Width [All] p1: maxlimit=100 minlimit=6 preferedwidth=10 minimp=50.000000 maximp=50.000000 favimp=50.000000
23 further rules are at their usual default settings.

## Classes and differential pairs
net class "Mounting Hole": MT1_2 MT2_2 MT_1_9 MT_2_9 MT_3_9 MT_4_9 MT_5_9 MT_6_9 MT_7_9 MT_8_9 NetJ4_MT1 NetJ4_MT2 NetJ5_MT1 NetJ5_MT2 NetJ6_MT1 NetJ6_MT2 NetJ7_MT1 NetJ7_MT2
channel class Short-Circuit-Logic-Integration: "Short Circuit Logic Intergration1" "Short Circuit Logic Intergration2" "Short Circuit Logic Intergration3" "Short Circuit Logic Intergration4"
component class "Solid State Switches4": C59_D C61_D D6_D D7_D Q3_D Q4_D Q8_D R63_D R83_D R89_D R91_D R104_D TP5_D U22_D
component class "Solid State Switches3": C59_C C61_C D6_C D7_C Q3_C Q4_C Q8_C R63_C R83_C R89_C R91_C R104_C TP5_C U22_C
component class "Solid State Switches2": C59_B C61_B D6_B D7_B Q3_B Q4_B Q8_B R63_B R83_B R89_B R91_B R104_B TP5_B U22_B
component class "Solid State Switches1": C59_A C61_A D6_A D7_A Q3_A Q4_A Q8_A R63_A R83_A R89_A R91_A R104_A TP5_A U22_A
channel class IN310_ISNS: "Short Circuit Current Sense1" "Short Circuit Current Sense2" "Short Circuit Current Sense3" "Short Circuit Current Sense4"
component class "Short Circuit Current Sense4": C48_D C49_D C50_D D8_D R62_D R93_D R94_D R98_D R102_D U18_D
component class "Short Circuit Current Sense3": C48_C C49_C C50_C D8_C R62_C R93_C R94_C R98_C R102_C U18_C
component class "Short Circuit Current Sense2": C48_B C49_B C50_B D8_B R62_B R93_B R94_B R98_B R102_B U18_B
component class "Short Circuit Current Sense1": C48_A C49_A C50_A D8_A R62_A R93_A R94_A R98_A R102_A U18_A
component class "Overcurrent Current Sense1": C10_A U4_A
net class CGND: CGND
net class "POSITIVE HIGHSIDE": NetC59_A_1 NetC59_B_1 NetC59_C_1 NetC59_D_1 NetU4_E_3
net class "RELAY OUTPUT": NetJ4_A NetJ4_B NetJ5_A NetJ5_B NetJ6_A NetJ6_B NetJ7_A NetJ7_B
net class "RELAY INPUT": N187 NetK1_A_1 NetK1_B_1 NetK1_C_1 NetK1_D_1
net class "MOSFET OUTPUT": GATE_DRV_HIGH_A GATE_DRV_HIGH_B GATE_DRV_HIGH_C GATE_DRV_HIGH_D ISO_RTN_A ISO_RTN_B ISO_RTN_C ISO_RTN_D NetD6_A_1 NetD6_B_1 NetD6_C_1 NetD6_D_1
net class "MOSFET INPUT": NetC59_A_1 NetC59_B_1 NetC59_C_1 NetC59_D_1
net class LV_NETCLASS: 24V_UNSWCH_BUS_CURRENT_3 BAYCAT_3V3_3 BOARD_TEMP_1 CGND CH-I_A CH-I_B CH-I_C CH-I_D CHA_CURRENT_SET_1 CHA_FET_EN_1 CHA_I_1 CHA_RLY_EN_1 CHB_CURRENT_SET_1 CHB_FET_EN_1 CHB_I_1 CHB_RLY_EN_1 CHC_CURRENT_SET_1 CHC_FET_EN_1 CHC_I_1 CHC_RLY_EN_1 CHD_CURRENT_SET_1 CHD_FET_EN_1 CHD_I_1 CHD_RLY_EN_1 COIL_DRV_HIGH_A DIO_SPARE_0_3 DIO_SPARE_1_3 DIO_SPARE_2_3 DIO_SPARE_3_3 DIO_SPARE_4_3 DIO_SPARE_5_3 DIO_SPARE_6_3 DIO_SPARE_7_3 FAULT_MUX_A FAULT_MUX_B FAULT_MUX_C FAULT_MUX_D FAULT_SENSE FAULT_SENSE_HCB_3 FAULT_SENSE_IN0 FAULT_SENSE_IN1 FAULT_SENSE_IN2 FAULT_SENSE_IN3 FAULT_SENSE_IN4 FAULT_SENSE_IN5 FAULT_SENSE_IN6 FAULT_SENSE_IN7 FAULT_SENSE_IPB1_3 FAULT_SENSE_IPB2_3 GF_AMP_TEMP_F_3 GF_ANNODE_SEL_EN_3 GF_CHASSIS_SEL_EN_3 GF_SIG_3 GF_SOURCE_SEL_A_3 GF_SOURCE_SEL_B_3 GF_SOURCE_SEL_C_3 GF_SOURCE_SEL_EN_3 HCB_MEDIA_EN_3 HPB_5V_CURRENT_3 HPB_5V_VOLTAGE_3 HPB_24V_CURRENT_3 HPB_24V_VOLTAGE_3 HPB_CISCO1_CURRENT_3 HPB_CISCO1_EN_3 HPB_CISCO2_CURRENT_3 HPB_CISCO2_EN_3 HPB_ISO24V_CURRENT_3 HPB_MEDIA_CURRENT_3 HPB_SYNCBOX_CURRENT_3 HPB_SYNCBOX_EN_3 HPB_TEMP0_3 HPB_TEMP1_3 HPB_TEMP2_3 HPB_TEMP3_3 HPB_TEMP4_3 HPB_VICOR1_TEMP_3 HPB_VICOR2_TEMP_3 HPB_VICOR3_TEMP_3 I2C_SCL_3 I2C_SDA_3 IGB_TEMP_F_3 INPUT-FAULT-RESET_1 INPUT_FET_LEFT_TEMP_F_3 INPUT_FET_RIGHT_TEMP_F_3 IPB1_BOARD_TEMP_3 IPB1_CHA_CURRENT_SET_3 IPB1_CHA_FET_EN_3 IPB1_CHA_I_3 IPB1_CHA_RLY_EN_3 IPB1_CHB_CURRENT_SET_3 IPB1_CHB_FET_EN_3 IPB1_CHB_I_3 IPB1_CHB_RLY_EN_3 IPB1_CHC_CURRENT_SET_3 IPB1_CHC_FET_EN_3 IPB1_CHC_I_3 IPB1_CHC_RLY_EN_3 IPB1_CHD_CURRENT_SET_3 IPB1_CHD_FET_EN_3 IPB1_CHD_I_3 IPB1_CHD_RLY_EN_3 IPB1_RESET_3 IPB2_BOARD_TEMP_3 IPB2_CHA_CURRENT_SET_3 IPB2_CHA_FET_EN_3 IPB2_CHA_I_3 IPB2_CHA_RLY_EN_3 IPB2_CHB_CURRENT_SET_3 IPB2_CHB_FET_EN_3 IPB2_CHB_I_3 IPB2_CHB_RLY_EN_3 IPB2_CHC_CURRENT_SET_3 IPB2_CHC_FET_EN_3 IPB2_CHC_I_3 IPB2_CHC_RLY_EN_3 IPB2_CHD_CURRENT_SET_3 IPB2_CHD_FET_EN_3 IPB2_CHD_I_3 IPB2_CHD_RLY_EN_3 IPB2_RESET_3 LV_GND LV_IGB_P24V LV_ISNS_P5V LV_ISNS_P12V LV_P5V LV_P12V MVC_L_CURRENT_3 MVC_L_VOLTAGE_3 MVC_R_CURRENT_3 MVC_R_VOLTAGE_3 NetC3_1 NetC6_1 NetC10_A_1 NetC10_B_1 NetC10_C_1 NetC10_D_1 NetC13_1 NetC13_2 NetC15_1 NetC43_1 NetC44_1 NetC46_2 NetC53_1 NetC54_1 NetC56_2 NetFB1_2 NetFB2_2 NetJ2_2 NetJ2_4 NetJ2_6 NetJ2_8 NetJ2_10 NetJ2_12 NetJ2_14 NetJ2_16 NetJ2_18 NetJ2_20 NetJ2_22 NetJ2_24 NetJ2_26 NetJ2_28 NetJ2_30 NetJ2_32 NetJ3_64 NetR1_2 NetR43_1 NetR43_2 NetR47_1 NetR47_2 NetR69_E_1 NetU1_1 NetU1_4 NetU1_5 NetU1_6 NetU1_7 NetU1_8 NetU5_6 V_DELAY_4 V_ISET_4
net class P187_REF: GATE_DRV_HIGH_A GATE_DRV_HIGH_B GATE_DRV_HIGH_C GATE_DRV_HIGH_D HV_P5V_A HV_P5V_B HV_P5V_C HV_P5V_D HV_P12V_A HV_P12V_B HV_P12V_C HV_P12V_D ISO_RTN_A ISO_RTN_B ISO_RTN_C ISO_RTN_D NetC59_A_1 NetC59_A_2 NetC59_B_1 NetC59_B_2 NetC59_C_1 NetC59_C_2 NetC59_D_1 NetC59_D_2 NetJ4_A NetJ5_A NetJ6_A NetJ7_A NetK1_A_1 NetK1_B_1 NetK1_C_1 NetK1_D_1 NetU4_E_3 P187 RELAY-TOP-NC_A RELAY-TOP-NC_B RELAY-TOP-NC_C RELAY-TOP-NC_D
net class N187_REF: N187 NetJ4_B NetJ5_B NetJ6_B NetJ7_B RELAY-BOTTOM-NC_A RELAY-BOTTOM-NC_B RELAY-BOTTOM-NC_C RELAY-BOTTOM-NC_D
channel class Solid_State_Switch: "Solid State Switches1" "Solid State Switches2" "Solid State Switches3" "Solid State Switches4"
component class "Short Circuit Logic Intergration4": C51_D Q5_D Q6_D Q7_D R76_D R84_D R90_D R92_D U21_D
component class "Short Circuit Logic Intergration3": C51_C Q5_C Q6_C Q7_C R76_C R84_C R90_C R92_C U21_C
component class "Short Circuit Logic Intergration2": C51_B Q5_B Q6_B Q7_B R76_B R84_B R90_B R92_B U21_B
component class "Short Circuit Logic Intergration1": C51_A Q5_A Q6_A Q7_A R76_A R84_A R90_A R92_A U21_A
component class "MOSFET HIGH Driver4": C21_D C?_G U6_D
component class "MOSFET HIGH Driver3": C21_C C?_E U6_C
component class "MOSFET HIGH Driver2": C21_B U6_B
component class "MOSFET HIGH Driver1": C21_A U6_A
component class "Channel Logic5": C28_E C29_E C30_E C31_E C32_E C34_E C35_E R70_E R71_E R72_E R73_E R74_E R75_E U9_E U10_E U11_E U12_E U13_E U14_E
channel class Relay_Driver: "Contactor Driver1" "Contactor Driver2" "Contactor Driver3" "Contactor Driver4" "Contactor Driver5" "Contactor Driver6" "Contactor Driver7" "Contactor Driver8"
channel class Isolated_Gate_Power_Supplies: "Isolated Gate Drive Power - HIGH1" "Isolated Gate Drive Power - HIGH2" "Isolated Gate Drive Power - HIGH3" "Isolated Gate Drive Power - HIGH4"
channel class Interface_Channel: "Interface Channel A" "Interface Channel B" "Interface Channel C" "Interface Channel D"
channel class Gate_Driver: "MOSFET HIGH Driver1" "MOSFET HIGH Driver2" "MOSFET HIGH Driver3" "MOSFET HIGH Driver4"
channel class FET_CH_Digital_Logic: "Channel Logic1" "Channel Logic2" "Channel Logic3" "Channel Logic4" "Channel Logic5"
channel class Current_Sense: "Current Sense" "Overcurrent Current Sense1" "Overcurrent Current Sense2" "Overcurrent Current Sense3" "Overcurrent Current Sense4"
channel class Anti_Alias_Filter: "Anti-Alias Filter1" "Anti-Alias Filter2" "Anti-Alias Filter3" "Anti-Alias Filter4"
channel class Analog_Current_Limit: "Current Limit - Configurable1" "Current Limit - Configurable2" "Current Limit - Configurable3" "Current Limit - Configurable4" "Current Limit - Configurable5"
channel class 12V_to_5V_ISNS_REFOUT: "12V to 5V (Linear) - ISNS Power1" "12V to 5V (Linear) - ISNS Power2" "12V to 5V (Linear) - ISNS Power3" "12V to 5V (Linear) - ISNS Power4" "12V to 5V (Linear) - ISNS Power5"
net class FAULT_SENSE_IN[7..0]: FAULT_SENSE_IN0 FAULT_SENSE_IN1 FAULT_SENSE_IN2 FAULT_SENSE_IN3 FAULT_SENSE_IN4 FAULT_SENSE_IN5 FAULT_SENSE_IN6 FAULT_SENSE_IN7
component class Top: C1 R1 R2 R95 R96 R97 U1
component class "Mezzanine Connector": J2 J3 R3 R4 R5 R6 R7 R8 R9 R10 R11 R12 R13 R14 R15 R16 R17 R18 R19 R20 R21 R22 R23 R24 R25 R26 R27 R28 R29 R30 R31 R32 R33 R34 R35 R36 R37 R38 R39 R40
component class Mechanical: FB1 FB2 MH1 MH2 MH3 MH4 MH5 MH6 MH7 MH8 MH9 MH10 MH11 MH13 MH14 MH15 MH16 MH17 MH18 MH19 MH20 MH21 MH23 MH25 MH26 MH27 MH28 MH29
component class "Local Low Voltage Power Supplies": C13 C14 C15 D2 D3 L1 Q1 R58 R59 R60
component class "Isolated Gate Drive Power - HIGH4": C16_D C17_D C18_D C19_D C20_D C33_D C47_D PS1_D R61_D U15_D
component class "Isolated Gate Drive Power - HIGH3": C16_C C17_C C18_C C19_C C20_C C33_C C47_C PS1_C R61_C U15_C
component class "Isolated Gate Drive Power - HIGH2": C16_B C17_B C18_B C19_B C20_B C33_B C47_B PS1_B R61_B U15_B
component class "Isolated Gate Drive Power - HIGH1": C16_A C17_A C18_A C19_A C20_A C33_A C47_A PS1_A R61_A U15_A
component class "Interface Channel D": C7_D C8_D C9_D D1_D K1_D K2_D R51_D R52_D R53_D R54_D R55_D R56_D R57_D R99_D R100_D R101_D R103_D TP4_D U3_D
component class "Interface Channel C": C7_C C8_C C9_C D1_C K1_C K2_C R51_C R52_C R53_C R54_C R55_C R56_C R57_C R99_C R100_C R101_C R103_C TP4_C U3_C
component class "Interface Channel B": C7_B C8_B C9_B D1_B K1_B K2_B R51_B R52_B R53_B R54_B R55_B R56_B R57_B R99_B R100_B R101_B R103_B TP4_B U3_B
component class "Interface Channel A": C7_A C8_A C9_A D1_A K1_A K2_A R51_A R52_A R53_A R54_A R55_A R56_A R57_A R99_A R100_A R101_A R103_A TP4_A U3_A
component class "Input Current Limit": C2 C3 C4 C5 C6 R41 R42 R43 R44 R45 R46 R47 R48 R49 R50 TP1 TP2 TP3 U2
component class "IGB Power Connector": J1
component class "Fault Multiplexer": C11 C12 U5
component class "External Interface Connectors": J4 J5 J6 J7
component class "Overcurrent Current Sense4": C10_D U4_D
component class "Overcurrent Current Sense3": C10_C U4_C
component class "Overcurrent Current Sense2": C10_B U4_B
component class "Current Sense": C10_E U4_E
component class "Current Limit - Configurable5": C22_E C23_E C24_E C25_E C26_E C27_E D5_E R66_E R67_E R68_E R69_E U7_E U8_E
component class "Current Limit - Configurable4": C22_D C23_D C24_D C25_D C26_D C27_D D5_D R66_D R67_D R68_D R69_D U7_D U8_D
component class "Current Limit - Configurable3": C22_C C23_C C24_C C25_C C26_C C27_C D5_C R66_C R67_C R68_C R69_C U7_C U8_C
component class "Current Limit - Configurable2": C22_B C23_B C24_B C25_B C26_B C27_B D5_B R66_B R67_B R68_B R69_B U7_B U8_B
component class "Current Limit - Configurable1": C22_A C23_A C24_A C25_A C26_A C27_A D5_A R66_A R67_A R68_A R69_A U7_A U8_A
component class "Contactor Driver8": D4_H Q2_H R64_H R65_H
component class "Contactor Driver7": D4_G Q2_G R64_G R65_G
component class "Contactor Driver6": D4_F Q2_F R64_F R65_F
component class "Contactor Driver5": D4_E Q2_E R64_E R65_E
component class "Contactor Driver4": D4_D Q2_D R64_D R65_D
component class "Contactor Driver3": D4_C Q2_C R64_C R65_C
component class "Contactor Driver2": D4_B Q2_B R64_B R65_B
component class "Contactor Driver1": D4_A Q2_A R64_A R65_A
component class "Channel Logic4": C28_D C29_D C30_D C31_D C32_D C34_D C35_D R70_D R71_D R72_D R73_D R74_D R75_D U9_D U10_D U11_D U12_D U13_D U14_D
component class "Channel Logic3": C28_C C29_C C30_C C31_C C32_C C34_C C35_C R70_C R71_C R72_C R73_C R74_C R75_C U9_C U10_C U11_C U12_C U13_C U14_C
component class "Channel Logic2": C28_B C29_B C30_B C31_B C32_B C34_B C35_B R70_B R71_B R72_B R73_B R74_B R75_B U9_B U10_B U11_B U12_B U13_B U14_B
component class "Channel Logic1": C28_A C29_A C30_A C31_A C32_A C34_A C35_A R70_A R71_A R72_A R73_A R74_A R75_A U9_A U10_A U11_A U12_A U13_A U14_A
component class "Anti-Alias Filter4": C36_D C37_D C38_D C39_D C40_D C41_D R77_D R78_D R79_D R80_D U16_D
component class "Anti-Alias Filter3": C36_C C37_C C38_C C39_C C40_C C41_C R77_C R78_C R79_C R80_C U16_C
component class "Anti-Alias Filter2": C36_B C37_B C38_B C39_B C40_B C41_B R77_B R78_B R79_B R80_B U16_B
component class "Anti-Alias Filter1": C36_A C37_A C38_A C39_A C40_A C41_A R77_A R78_A R79_A R80_A U16_A
component class "24 to 12V (DC/DC)": C52 C53 C54 C55 C56 L4 R85 R86 U19
component class "24 to 5V (DC/DC) - 5V Logic": C42 C43 C44 C45 C46 L2 R81 R82 U17
component class "12V to 5V (Linear) - ISNS Power5": C57_E C58_E R87_E R88_E U20_E
component class "12V to 5V (Linear) - ISNS Power4": C57_D C58_D R87_D R88_D U20_D
component class "12V to 5V (Linear) - ISNS Power3": C57_C C58_C R87_C R88_C U20_C
component class "12V to 5V (Linear) - ISNS Power2": C57_B C58_B R87_B R88_B U20_B
component class "12V to 5V (Linear) - ISNS Power1": C57_A C58_A R87_A R88_A U20_A

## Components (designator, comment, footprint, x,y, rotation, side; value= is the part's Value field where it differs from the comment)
C1 "Capacitor 100nF +/- 10%, 50V, X7R, 0603" CAPC1608X90X40ML10T20 6575,6863.43 r270 top value=100nF
C2 "Capacitor 100 nF +/-10% 50 V 0805" CAPC2013X95X50ML10T25 5565,10880 r90 top value=100nF
C3 "Capacitor 1nF +/- 5%, 50V, C0G, 0603" CAPC1608X90X40ML10T20 4682.2,10455 r0 top value=1nF
C4 "Capacitor 10nF +/- 5%, 50V, C0G, 0603" CAPC1608X90X40ML10T20 4335,10172.95 r90 top value=10nF
C5 "Capacitor 1 uF +/- 10% 16 V 0603" CAPC1608X94X35NL15T15 4255,10170 r90 top value=1µF
C6 "Capacitor 1nF +/- 5%, 50V, C0G, 0603" CAPC1608X90X40ML10T20 4173.43,10510 r180 top value=1nF
C7_A "Capacitor 10nF +/- 5%, 50V, C0G, 0603" CAPC1608X90X40ML10T20 5332.95,1450 r180 top value=10nF (schematic designator C7)
C7_B "Capacitor 10nF +/- 5%, 50V, C0G, 0603" CAPC1608X90X40ML10T20 5332.95,4450 r180 top value=10nF (schematic designator C7)
C7_C "Capacitor 10nF +/- 5%, 50V, C0G, 0603" CAPC1608X90X40ML10T20 5332.95,7450 r180 top value=10nF (schematic designator C7)
C7_D "Capacitor 10nF +/- 5%, 50V, C0G, 0603" CAPC1608X90X40ML10T20 5332.95,10450 r180 top value=10nF (schematic designator C7)
C8_A "Capacitor 1 uF +/- 10% 16 V 0603" CAPC1608X94X35NL15T15 5330,1370 r0 top value=1µF (schematic designator C8)
C8_B "Capacitor 1 uF +/- 10% 16 V 0603" CAPC1608X94X35NL15T15 5330,4370 r0 top value=1µF (schematic designator C8)
C8_C "Capacitor 1 uF +/- 10% 16 V 0603" CAPC1608X94X35NL15T15 5330,7370 r0 top value=1µF (schematic designator C8)
C8_D "Capacitor 1 uF +/- 10% 16 V 0603" CAPC1608X94X35NL15T15 5330,10370 r0 top value=1µF (schematic designator C8)
C9_A "Capacitor 1nF +/-20% 50V 0402" CAPC0402(1005)33_L 5778.35,1640 r180 top value=1nF (schematic designator C9)
C9_B "Capacitor 1nF +/-20% 50V 0402" CAPC0402(1005)33_L 5778.35,4640 r180 top value=1nF (schematic designator C9)
C9_C "Capacitor 1nF +/-20% 50V 0402" CAPC0402(1005)33_L 5778.35,7640 r180 top value=1nF (schematic designator C9)
C9_D "Capacitor 1nF +/-20% 50V 0402" CAPC0402(1005)33_L 5778.35,10640 r180 top value=1nF (schematic designator C9)
C10_A "Capacitor 100nF +/- 10%, 50V, X7R, 0603" CAPC1608X90X40ML10T20 9278.77,2821.23 r90 top value=100nF (schematic designator C10)
C10_B "Capacitor 100nF +/- 10%, 50V, X7R, 0603" CAPC1608X90X40ML10T20 9280,5820 r90 top value=100nF (schematic designator C10)
C10_C "Capacitor 100nF +/- 10%, 50V, X7R, 0603" CAPC1608X90X40ML10T20 9280,8816.57 r90 top value=100nF (schematic designator C10)
C10_D "Capacitor 100nF +/- 10%, 50V, X7R, 0603" CAPC1608X90X40ML10T20 9290,11821.57 r90 top value=100nF (schematic designator C10)
C10_E "Capacitor 100nF +/- 10%, 50V, X7R, 0603" CAPC1608X90X40ML10T20 13400,11910 r0 bottom value=100nF (schematic designator C10)
C11 "Capacitor 1uF 10%, 50V, X7R, 1210" CAPC3225X270X30ML30 1720,1334.65 r270 top value=1uF
C12 "Capacitor 100nF +/- 10%, 50V, X7R, 0603" CAPC1608X90X40ML10T20 1575,1375.99 r90 top value=100nF
C13 "Capacitor 4.7uF 10%, 50V, X7R, 1210" CAPC3225X270X30ML30 822.8,8971.34 r180 top value=4.7uF
C14 "Capacitor 1uF 10%, 50V, X7R, 1210" CAPC3225X270X30ML30 2830,5173.42 r270 top value=1uF
C15 "Capacitor 4.7uF 10%, 50V, X7R, 1210" CAPC3225X270X30ML30 2655,5030.31 r270 top value=4.7uF
C16_A "C1206X102KGRACAUTO" FP-C1206X102KGRACAUTO-IPC_A 8215.94,1850 r0 top value=1nF (schematic designator C16)
C16_B "C1206X102KGRACAUTO" FP-C1206X102KGRACAUTO-IPC_A 8215.94,4850 r0 top value=1nF (schematic designator C16)
C16_C "C1206X102KGRACAUTO" FP-C1206X102KGRACAUTO-IPC_A 8215.94,7850 r0 top value=1nF (schematic designator C16)
C16_D "C1206X102KGRACAUTO" FP-C1206X102KGRACAUTO-IPC_A 8215.94,10850 r0 top value=1nF (schematic designator C16)
C17_A "T491X226K050AT" FP-T491X226K050AT-MFG 8090,2624.68 r270 top value=22uF (schematic designator C17)
C17_B "T491X226K050AT" FP-T491X226K050AT-MFG 8090,5624.68 r270 top value=22uF (schematic designator C17)
C17_C "T491X226K050AT" FP-T491X226K050AT-MFG 8090,8624.68 r270 top value=22uF (schematic designator C17)
C17_D "T491X226K050AT" FP-T491X226K050AT-MFG 8100,11575 r270 top value=22uF (schematic designator C17)
C18_A "T491X226K050AT" FP-T491X226K050AT-MFG 7880,2624.68 r270 top value=22uF (schematic designator C18)
C18_B "T491X226K050AT" FP-T491X226K050AT-MFG 7880,5624.68 r270 top value=22uF (schematic designator C18)
C18_C "T491X226K050AT" FP-T491X226K050AT-MFG 7880,8624.68 r270 top value=22uF (schematic designator C18)
C18_D "T491X226K050AT" FP-T491X226K050AT-MFG 7900,11575 r270 top value=22uF (schematic designator C18)
C19_A "T491X226K050AT" FP-T491X226K050AT-MFG 8500,2425 r180 top value=22uF (schematic designator C19)
C19_B "T491X226K050AT" FP-T491X226K050AT-MFG 8500,5425 r180 top value=22uF (schematic designator C19)
C19_C "T491X226K050AT" FP-T491X226K050AT-MFG 8500,8425 r180 top value=22uF (schematic designator C19)
C19_D "T491X226K050AT" FP-T491X226K050AT-MFG 8500,11425 r180 top value=22uF (schematic designator C19)
C20_A "C1206X102KGRACAUTO" FP-C1206X102KGRACAUTO-IPC_A 8775,2590 r270 top value=1nF (schematic designator C20)
C20_B "C1206X102KGRACAUTO" FP-C1206X102KGRACAUTO-IPC_A 8775,5590 r270 top value=1nF (schematic designator C20)
C20_C "C1206X102KGRACAUTO" FP-C1206X102KGRACAUTO-IPC_A 8775,8590 r270 top value=1nF (schematic designator C20)
C20_D "C1206X102KGRACAUTO" FP-C1206X102KGRACAUTO-IPC_A 8775,11540 r270 top value=1nF (schematic designator C20)
C21_A "Capacitor 10uF 10%, 50V, X7R, 1210" CAPC3225X270X30ML30 9725,595 r90 top value=10uF (schematic designator C21)
C21_B "Capacitor 10uF 10%, 50V, X7R, 1210" CAPC3225X270X30ML30 9723.42,3578.66 r90 top value=10uF (schematic designator C21)
C21_C "Capacitor 10uF 10%, 50V, X7R, 1210" CAPC3225X270X30ML30 9715,6577.09 r90 top value=10uF (schematic designator C21)
C21_D "Capacitor 10uF 10%, 50V, X7R, 1210" CAPC3225X270X30ML30 9730.9,9591.26 r90 top value=10uF (schematic designator C21)
C22_A "Capacitor 10nF +/- 5%, 50V, C0G, 0603" CAPC1608X90X40ML10T20 6380,1335 r90 top value=10nF (schematic designator C22)
C22_B "Capacitor 10nF +/- 5%, 50V, C0G, 0603" CAPC1608X90X40ML10T20 6380,4335 r90 top value=10nF (schematic designator C22)
C22_C "Capacitor 10nF +/- 5%, 50V, C0G, 0603" CAPC1608X90X40ML10T20 6355,7160 r90 top value=10nF (schematic designator C22)
C22_D "Capacitor 10nF +/- 5%, 50V, C0G, 0603" CAPC1608X90X40ML10T20 6380,10285 r90 top value=10nF (schematic designator C22)
C22_E "Capacitor 10nF +/- 5%, 50V, C0G, 0603" CAPC1608X90X40ML10T20 4520,10910 r90 top value=10nF (schematic designator C22)
C23_A "Capacitor 1 uF +/- 10% 16 V 0603" CAPC1608X94X35NL15T15 6450,1335 r90 top value=1µF (schematic designator C23)
C23_B "Capacitor 1 uF +/- 10% 16 V 0603" CAPC1608X94X35NL15T15 6450,4335 r90 top value=1µF (schematic designator C23)
C23_C "Capacitor 1 uF +/- 10% 16 V 0603" CAPC1608X94X35NL15T15 6425,7160 r90 top value=1µF (schematic designator C23)
C23_D "Capacitor 1 uF +/- 10% 16 V 0603" CAPC1608X94X35NL15T15 6450,10285 r90 top value=1µF (schematic designator C23)
C23_E "Capacitor 1 uF +/- 10% 16 V 0603" CAPC1608X94X35NL15T15 4590,10910 r90 top value=1µF (schematic designator C23)
C24_A "Capacitor 1nF +/- 5%, 50V, C0G, 0603" CAPC1608X90X40ML10T20 6310,1795 r90 top value=1nF (schematic designator C24)
C24_B "Capacitor 1nF +/- 5%, 50V, C0G, 0603" CAPC1608X90X40ML10T20 6310,4795 r90 top value=1nF (schematic designator C24)
C24_C "Capacitor 1nF +/- 5%, 50V, C0G, 0603" CAPC1608X90X40ML10T20 6285,7620 r90 top value=1nF (schematic designator C24)
C24_D "Capacitor 1nF +/- 5%, 50V, C0G, 0603" CAPC1608X90X40ML10T20 6310,10745 r90 top value=1nF (schematic designator C24)
C24_E "Capacitor 1nF +/- 5%, 50V, C0G, 0603" CAPC1608X90X40ML10T20 4450,11370 r90 top value=1nF (schematic designator C24)
C25_A "Capacitor 100 nF +/-10% 50 V 0805" CAPC2013X95X50ML10T25 6080,1395 r0 top value=100nF (schematic designator C25)
C25_B "Capacitor 100 nF +/-10% 50 V 0805" CAPC2013X95X50ML10T25 6080,4395 r0 top value=100nF (schematic designator C25)
C25_C "Capacitor 100 nF +/-10% 50 V 0805" CAPC2013X95X50ML10T25 6055,7220 r0 top value=100nF (schematic designator C25)
C25_D "Capacitor 100 nF +/-10% 50 V 0805" CAPC2013X95X50ML10T25 6080,10345 r0 top value=100nF (schematic designator C25)
C25_E "Capacitor 100 nF +/-10% 50 V 0805" CAPC2013X95X50ML10T25 4220,10970 r0 top value=100nF (schematic designator C25)
C26_A "Capacitor 1nF +/- 5%, 50V, C0G, 0603" CAPC1608X90X40ML10T20 6230,1795 r90 top value=1nF (schematic designator C26)
C26_B "Capacitor 1nF +/- 5%, 50V, C0G, 0603" CAPC1608X90X40ML10T20 6230,4795 r90 top value=1nF (schematic designator C26)
C26_C "Capacitor 1nF +/- 5%, 50V, C0G, 0603" CAPC1608X90X40ML10T20 6205,7620 r90 top value=1nF (schematic designator C26)
C26_D "Capacitor 1nF +/- 5%, 50V, C0G, 0603" CAPC1608X90X40ML10T20 6230,10745 r90 top value=1nF (schematic designator C26)
C26_E "Capacitor 1nF +/- 5%, 50V, C0G, 0603" CAPC1608X90X40ML10T20 4370,11370 r90 top value=1nF (schematic designator C26)
C27_A "Capacitor 100 nF +/-10% 50 V 0805" CAPC2013X95X50ML10T25 6490,1795 r270 top value=100nF (schematic designator C27)
C27_B "Capacitor 100 nF +/-10% 50 V 0805" CAPC2013X95X50ML10T25 6490,4795 r270 top value=100nF (schematic designator C27)
C27_C "Capacitor 100 nF +/-10% 50 V 0805" CAPC2013X95X50ML10T25 6465,7620 r270 top value=100nF (schematic designator C27)
C27_D "Capacitor 100 nF +/-10% 50 V 0805" CAPC2013X95X50ML10T25 6490,10745 r270 top value=100nF (schematic designator C27)
C27_E "Capacitor 100 nF +/-10% 50 V 0805" CAPC2013X95X50ML10T25 4630,11370 r270 top value=100nF (schematic designator C27)
C28_A "Capacitor 100 nF +/-10% 50 V 0805" CAPC2013X95X50ML10T25 6915,1580 r90 top value=100nF (schematic designator C28)
C28_B "Capacitor 100 nF +/-10% 50 V 0805" CAPC2013X95X50ML10T25 6865,4555 r90 top value=100nF (schematic designator C28)
C28_C "Capacitor 100 nF +/-10% 50 V 0805" CAPC2013X95X50ML10T25 6840,7380 r90 top value=100nF (schematic designator C28)
C28_D "Capacitor 100 nF +/-10% 50 V 0805" CAPC2013X95X50ML10T25 6866.54,10505 r90 top value=100nF (schematic designator C28)
C28_E "Capacitor 100 nF +/-10% 50 V 0805" CAPC2013X95X50ML10T25 5090,11130 r90 top value=100nF (schematic designator C28)
C29_A "Capacitor 100nF +/- 10%, 50V, X7R, 0603" CAPC1608X90X40ML10T20 7275,1755 r90 bottom value=100nF (schematic designator C29)
C29_B "Capacitor 100nF +/- 10%, 50V, X7R, 0603" CAPC1608X90X40ML10T20 7225,4730 r90 bottom value=100nF (schematic designator C29)
C29_C "Capacitor 100nF +/- 10%, 50V, X7R, 0603" CAPC1608X90X40ML10T20 7200,7555 r90 bottom value=100nF (schematic designator C29)
C29_D "Capacitor 100nF +/- 10%, 50V, X7R, 0603" CAPC1608X90X40ML10T20 7226.54,10680 r90 bottom value=100nF (schematic designator C29)
C29_E "Capacitor 100nF +/- 10%, 50V, X7R, 0603" CAPC1608X90X40ML10T20 5450,11305 r90 bottom value=100nF (schematic designator C29)
C30_A "Capacitor 100nF +/- 10%, 50V, X7R, 0603" CAPC1608X90X40ML10T20 7002,1836 r180 top value=100nF (schematic designator C30)
C30_B "Capacitor 100nF +/- 10%, 50V, X7R, 0603" CAPC1608X90X40ML10T20 6952,4811 r180 top value=100nF (schematic designator C30)
C30_C "Capacitor 100nF +/- 10%, 50V, X7R, 0603" CAPC1608X90X40ML10T20 6927,7636 r180 top value=100nF (schematic designator C30)
C30_D "Capacitor 100nF +/- 10%, 50V, X7R, 0603" CAPC1608X90X40ML10T20 6953.54,10761 r180 top value=100nF (schematic designator C30)
C30_E "Capacitor 100nF +/- 10%, 50V, X7R, 0603" CAPC1608X90X40ML10T20 5177,11386 r180 top value=100nF (schematic designator C30)
C31_A "Capacitor 100nF +/- 10%, 50V, X7R, 0603" CAPC1608X90X40ML10T20 7155,1330 r180 top value=100nF (schematic designator C31)
C31_B "Capacitor 100nF +/- 10%, 50V, X7R, 0603" CAPC1608X90X40ML10T20 7105,4305 r180 top value=100nF (schematic designator C31)
C31_C "Capacitor 100nF +/- 10%, 50V, X7R, 0603" CAPC1608X90X40ML10T20 7080,7130 r180 top value=100nF (schematic designator C31)
C31_D "Capacitor 100nF +/- 10%, 50V, X7R, 0603" CAPC1608X90X40ML10T20 7106.54,10255 r180 top value=100nF (schematic designator C31)
C31_E "Capacitor 100nF +/- 10%, 50V, X7R, 0603" CAPC1608X90X40ML10T20 5330,10880 r180 top value=100nF (schematic designator C31)
C32_A "Capacitor 100nF +/- 10%, 50V, X7R, 0603" CAPC1608X90X40ML10T20 7555,1555 r90 top value=100nF (schematic designator C32)
C32_B "Capacitor 100nF +/- 10%, 50V, X7R, 0603" CAPC1608X90X40ML10T20 7505,4530 r90 top value=100nF (schematic designator C32)
C32_C "Capacitor 100nF +/- 10%, 50V, X7R, 0603" CAPC1608X90X40ML10T20 7480,7355 r90 top value=100nF (schematic designator C32)
C32_D "Capacitor 100nF +/- 10%, 50V, X7R, 0603" CAPC1608X90X40ML10T20 7506.54,10480 r90 top value=100nF (schematic designator C32)
C32_E "Capacitor 100nF +/- 10%, 50V, X7R, 0603" CAPC1608X90X40ML10T20 5730,11105 r90 top value=100nF (schematic designator C32)
C33_A "885012107016" WCAP-CSGP_0805_L2W1.25H1.25 8825,1550 r270 top (schematic designator C33)
C33_B "885012107016" WCAP-CSGP_0805_L2W1.25H1.25 9535.91,4390 r180 top (schematic designator C33)
C33_C "885012107016" WCAP-CSGP_0805_L2W1.25H1.25 9535.91,7390 r180 top (schematic designator C33)
C33_D "885012107016" WCAP-CSGP_0805_L2W1.25H1.25 9535.91,10390 r180 top (schematic designator C33)
C34_A "Capacitor 100nF +/- 10%, 50V, X7R, 0603" CAPC1608X90X40ML10T20 7255,1405 r0 top value=100nF (schematic designator C34)
C34_B "Capacitor 100nF +/- 10%, 50V, X7R, 0603" CAPC1608X90X40ML10T20 7205,4380 r0 top value=100nF (schematic designator C34)
C34_C "Capacitor 100nF +/- 10%, 50V, X7R, 0603" CAPC1608X90X40ML10T20 7180,7205 r0 top value=100nF (schematic designator C34)
C34_D "Capacitor 100nF +/- 10%, 50V, X7R, 0603" CAPC1608X90X40ML10T20 7206.54,10330 r0 top value=100nF (schematic designator C34)
C34_E "Capacitor 100nF +/- 10%, 50V, X7R, 0603" CAPC1608X90X40ML10T20 5430,10955 r0 top value=100nF (schematic designator C34)
C35_A "Capacitor 100nF +/- 10%, 50V, X7R, 0603" CAPC1608X90X40ML10T20 7530,1840 r180 top value=100nF (schematic designator C35)
C35_B "Capacitor 100nF +/- 10%, 50V, X7R, 0603" CAPC1608X90X40ML10T20 7480,4815 r180 top value=100nF (schematic designator C35)
C35_C "Capacitor 100nF +/- 10%, 50V, X7R, 0603" CAPC1608X90X40ML10T20 7455,7640 r180 top value=100nF (schematic designator C35)
C35_D "Capacitor 100nF +/- 10%, 50V, X7R, 0603" CAPC1608X90X40ML10T20 7481.54,10765 r180 top value=100nF (schematic designator C35)
C35_E "Capacitor 100nF +/- 10%, 50V, X7R, 0603" CAPC1608X90X40ML10T20 5705,11390 r180 top value=100nF (schematic designator C35)
C36_A "Capacitor 10nF +/- 5%, 50V, C0G, 0603" CAPC1608X90X40ML10T20 6060,2095 r270 top value=10nF (schematic designator C36)
C36_B "Capacitor 10nF +/- 5%, 50V, C0G, 0603" CAPC1608X90X40ML10T20 6060,5070 r270 top value=10nF (schematic designator C36)
C36_C "Capacitor 10nF +/- 5%, 50V, C0G, 0603" CAPC1608X90X40ML10T20 6060,8070 r270 top value=10nF (schematic designator C36)
C36_D "Capacitor 10nF +/- 5%, 50V, C0G, 0603" CAPC1608X90X40ML10T20 6085,11010 r270 top value=10nF (schematic designator C36)
C37_A "Capacitor 1 uF +/- 10% 16 V 0603" CAPC1608X94X35NL15T15 6135,2095 r90 top value=1µF (schematic designator C37)
C37_B "Capacitor 1 uF +/- 10% 16 V 0603" CAPC1608X94X35NL15T15 6135,5070 r90 top value=1µF (schematic designator C37)
C37_C "Capacitor 1 uF +/- 10% 16 V 0603" CAPC1608X94X35NL15T15 6135,8070 r90 top value=1µF (schematic designator C37)
C37_D "Capacitor 1 uF +/- 10% 16 V 0603" CAPC1608X94X35NL15T15 6160,11010 r90 top value=1µF (schematic designator C37)
C38_A "CGA5L1X7R1E685K160AC" FP-CGA5L-0_3-0_1-IPC_A 6223.28,2265 r270 bottom value=6.8uF (schematic designator C38)
C38_B "CGA5L1X7R1E685K160AC" FP-CGA5L-0_3-0_1-IPC_A 6223.28,5240 r270 bottom value=6.8uF (schematic designator C38)
C38_C "CGA5L1X7R1E685K160AC" FP-CGA5L-0_3-0_1-IPC_A 6223.28,8240 r270 bottom value=6.8uF (schematic designator C38)
C38_D "CGA5L1X7R1E685K160AC" FP-CGA5L-0_3-0_1-IPC_A 6248.28,11180 r270 bottom value=6.8uF (schematic designator C38)
C39_A "C0805C125K8RAC7800" CAPC2012X11M 6409.21,2185 r180 top value=1.2uF (schematic designator C39)
C39_B "C0805C125K8RAC7800" CAPC2012X11M 6422.99,5160 r180 top value=1.2uF (schematic designator C39)
C39_C "C0805C125K8RAC7800" CAPC2012X11M 6407.72,8145 r180 top value=1.2uF (schematic designator C39)
C39_D "C0805C125K8RAC7800" CAPC2012X11M 6434.21,11100 r180 top value=1.2uF (schematic designator C39)
C40_A "Capacitor 1 uF +/- 10% 16 V 0603" CAPC1608X94X35NL15T15 6349.21,2305 r270 top value=1µF (schematic designator C40)
C40_B "Capacitor 1 uF +/- 10% 16 V 0603" CAPC1608X94X35NL15T15 6349.21,5280 r270 top value=1µF (schematic designator C40)
C40_C "Capacitor 1 uF +/- 10% 16 V 0603" CAPC1608X94X35NL15T15 6349.21,8280 r270 top value=1µF (schematic designator C40)
C40_D "Capacitor 1 uF +/- 10% 16 V 0603" CAPC1608X94X35NL15T15 6374.21,11220 r270 top value=1µF (schematic designator C40)
C41_A "Capacitor 1 uF +/- 10% 16 V 0603" CAPC1608X94X35NL15T15 5987.75,2295 r90 bottom value=1µF (schematic designator C41)
C41_B "Capacitor 1 uF +/- 10% 16 V 0603" CAPC1608X94X35NL15T15 5987.75,5270 r90 bottom value=1µF (schematic designator C41)
C41_C "Capacitor 1 uF +/- 10% 16 V 0603" CAPC1608X94X35NL15T15 5987.75,8270 r90 bottom value=1µF (schematic designator C41)
C41_D "Capacitor 1 uF +/- 10% 16 V 0603" CAPC1608X94X35NL15T15 6012.75,11210 r90 bottom value=1µF (schematic designator C41)
C42 "T491D106K050AT" KEMT-D-7343-31-2_L 2255,7340 r90 top value=10uF
C43 "T491D106K050AT" KEMT-D-7343-31-2_L 1425,7540 r0 top value=10uF
C44 "T491D106K050AT" KEMT-D-7343-31-2_L 1895,6765 r180 top value=10uF
C45 "Capacitor 4.7uF 10%, 50V, X7R, 1210" CAPC3225X270X30ML30 1500,7306.14 r270 top value=4.7uF
C46 "Capacitor 4.7uF 10%, 50V, X7R, 1210" CAPC3225X270X30ML30 1755,7031.14 r90 top value=4.7uF
C47_A "885012107016" WCAP-CSGP_0805_L2W1.25H1.25 9225,1550 r270 top (schematic designator C47)
C47_B "885012107016" WCAP-CSGP_0805_L2W1.25H1.25 9535.91,3990 r180 top (schematic designator C47)
C47_C "885012107016" WCAP-CSGP_0805_L2W1.25H1.25 9535.91,6990 r180 top (schematic designator C47)
C47_D "885012107016" WCAP-CSGP_0805_L2W1.25H1.25 9535.91,9990 r180 top (schematic designator C47)
C48_A "885012207072" WCAP-CSGP_0805_L2W1.25H0.8_Reflow 10612.6,500 r0 top (schematic designator C48)
C48_B "885012207072" WCAP-CSGP_0805_L2W1.25H0.8_Reflow 10612.6,3500.2 r0 top (schematic designator C48)
C48_C "885012207072" WCAP-CSGP_0805_L2W1.25H0.8_Reflow 10612.6,6500.2 r0 top (schematic designator C48)
C48_D "885012207072" WCAP-CSGP_0805_L2W1.25H0.8_Reflow 10611.57,9500 r0 top (schematic designator C48)
C49_A "885012207072" WCAP-CSGP_0805_L2W1.25H0.8_Reflow 10550,812.4 r270 top (schematic designator C49)
C49_B "885012207072" WCAP-CSGP_0805_L2W1.25H0.8_Reflow 10550,3812.6 r270 top (schematic designator C49)
C49_C "885012207072" WCAP-CSGP_0805_L2W1.25H0.8_Reflow 10550,6812.6 r270 top (schematic designator C49)
C49_D "885012207072" WCAP-CSGP_0805_L2W1.25H0.8_Reflow 10548.98,9812.4 r270 top (schematic designator C49)
C50_A "885012107015" WCAP-CSGP_0805_L2W1.25H1.25 10625,812.4 r270 top (schematic designator C50)
C50_B "885012107015" WCAP-CSGP_0805_L2W1.25H1.25 10625,3812.6 r270 top (schematic designator C50)
C50_C "885012107015" WCAP-CSGP_0805_L2W1.25H1.25 10625,6812.6 r270 top (schematic designator C50)
C50_D "885012107015" WCAP-CSGP_0805_L2W1.25H1.25 10623.98,9812.4 r270 top (schematic designator C50)
C51_A "885012207072" WCAP-CSGP_0805_L2W1.25H0.8_Reflow 8695,800 r180 top (schematic designator C51)
C51_B "885012207072" WCAP-CSGP_0805_L2W1.25H0.8_Reflow 8684.76,3783.66 r180 top (schematic designator C51)
C51_C "885012207072" WCAP-CSGP_0805_L2W1.25H0.8_Reflow 8693.42,6783.66 r180 top (schematic designator C51)
C51_D "885012207072" WCAP-CSGP_0805_L2W1.25H0.8_Reflow 8693.42,9783.66 r180 top (schematic designator C51)
C52 "T491D106K050AT" KEMT-D-7343-31-2_L 2255,6235 r90 top value=10uF
C53 "T491D106K050AT" KEMT-D-7343-31-2_L 1425,6435 r0 top value=10uF
C54 "T491D106K050AT" KEMT-D-7343-31-2_L 1895,5660 r180 top value=10uF
C55 "Capacitor 4.7uF 10%, 50V, X7R, 1210" CAPC3225X270X30ML30 1500,6200 r270 top value=4.7uF
C56 "Capacitor 4.7uF 10%, 50V, X7R, 1210" CAPC3225X270X30ML30 1755,5925 r90 top value=4.7uF
C57_A "Capacitor 100nF +/- 10%, 50V, X7R, 0603" CAPC1608X90X40ML10T20 6860.24,2070.25 r0 bottom value=100nF (schematic designator C57)
C57_B "Capacitor 100nF +/- 10%, 50V, X7R, 0603" CAPC1608X90X40ML10T20 6860.24,5072.19 r0 bottom value=100nF (schematic designator C57)
C57_C "Capacitor 100nF +/- 10%, 50V, X7R, 0603" CAPC1608X90X40ML10T20 6915,9097.64 r180 bottom value=100nF (schematic designator C57)
C57_D "Capacitor 100nF +/- 10%, 50V, X7R, 0603" CAPC1608X90X40ML10T20 6810.24,10850.25 r0 bottom value=100nF (schematic designator C57)
C57_E "Capacitor 100nF +/- 10%, 50V, X7R, 0603" CAPC1608X90X40ML10T20 6874.88,9835.36 r90 bottom value=100nF (schematic designator C57)
C58_A "Capacitor 1uF 10%, 50V, X7R, 0805" CAPC2013X95X50ML10T25 6975.24,2551.46 r90 bottom value=1uF (schematic designator C58)
C58_B "Capacitor 1uF 10%, 50V, X7R, 0805" CAPC2013X95X50ML10T25 6975.24,5553.41 r90 bottom value=1uF (schematic designator C58)
C58_C "Capacitor 1uF 10%, 50V, X7R, 0805" CAPC2013X95X50ML10T25 6800,8616.42 r270 bottom value=1uF (schematic designator C58)
C58_D "Capacitor 1uF 10%, 50V, X7R, 0805" CAPC2013X95X50ML10T25 6925.24,11331.47 r90 bottom value=1uF (schematic designator C58)
C58_E "Capacitor 1uF 10%, 50V, X7R, 0805" CAPC2013X95X50ML10T25 6393.66,9950.36 r180 bottom value=1uF (schematic designator C58)
C59_A "R76QI222050H4J" R76QI222050H4J-Footprint-1 10150,2775 r0 top value=22nF (schematic designator C59)
C59_B "R76QI222050H4J" R76QI222050H4J-Footprint-1 10150,5750 r0 top value=22nF (schematic designator C59)
C59_C "R76QI222050H4J" R76QI222050H4J-Footprint-1 10150,8750 r0 top value=22nF (schematic designator C59)
C59_D "R76QI222050H4J" R76QI222050H4J-Footprint-1 10150,11775 r0 top value=22nF (schematic designator C59)
C61_A "885012207072" WCAP-CSGP_0805_L2W1.25H0.8_Reflow 11025,400 r270 top (schematic designator C61)
C61_B "885012207072" WCAP-CSGP_0805_L2W1.25H0.8_Reflow 11025,3425 r270 top (schematic designator C61)
C61_C "885012207072" WCAP-CSGP_0805_L2W1.25H0.8_Reflow 11025,6425 r270 top (schematic designator C61)
C61_D "885012207072" WCAP-CSGP_0805_L2W1.25H0.8_Reflow 11023.98,9425 r270 top (schematic designator C61)
D1_A "VS-8EWS16SLHM3" TO-252AA-IPC_A-APL 13350,1050 r90 top (schematic designator D1)
D1_B "VS-8EWS16SLHM3" TO-252AA-IPC_A-APL 13350,4050 r90 top (schematic designator D1)
D1_C "VS-8EWS16SLHM3" TO-252AA-IPC_A-APL 13350,7050 r90 top (schematic designator D1)
D1_D "VS-8EWS16SLHM3" TO-252AA-IPC_A-APL 13350,10050 r90 top (schematic designator D1)
D2 "NRVBAF3200T3G" DIOM4326X11M 754.88,9210 r270 top
D3 "SZMMSZ15ET1G" ONSC-SOD-123-2-425-04_V 822.8,8821.34 r0 top
D4_A "PMEG4010CEJ115" SODFL250X80-2M 7179.72,2450 r0 top (schematic designator D4)
D4_B "PMEG4010CEJ115" SODFL250X80-2M 7529.72,2450 r0 top (schematic designator D4)
D4_C "PMEG4010CEJ115" SODFL250X80-2M 7179.72,5450 r0 top (schematic designator D4)
D4_D "PMEG4010CEJ115" SODFL250X80-2M 7529.72,5450 r0 top (schematic designator D4)
D4_E "PMEG4010CEJ115" SODFL250X80-2M 7179.72,8450 r0 top (schematic designator D4)
D4_F "PMEG4010CEJ115" SODFL250X80-2M 7529.72,8450 r0 top (schematic designator D4)
D4_G "PMEG4010CEJ115" SODFL250X80-2M 7179.72,11450 r0 top (schematic designator D4)
D4_H "PMEG4010CEJ115" SODFL250X80-2M 7535,11450 r0 top (schematic designator D4)
D5_A "1N4148WS" FAIR-SOD-323_V 6080,1305 r180 top (schematic designator D5)
D5_B "1N4148WS" FAIR-SOD-323_V 6080,4305 r180 top (schematic designator D5)
D5_C "1N4148WS" FAIR-SOD-323_V 6055,7130 r180 top (schematic designator D5)
D5_D "1N4148WS" FAIR-SOD-323_V 6080,10255 r180 top (schematic designator D5)
D5_E "1N4148WS" FAIR-SOD-323_V 4220,10880 r180 top (schematic designator D5)
D6_A "SZMMSZ15ET1G" ONSC-SOD-123-2-425-04_V 10200,1325 r0 top (schematic designator D6)
D6_B "SZMMSZ15ET1G" ONSC-SOD-123-2-425-04_V 10200,4325 r0 top (schematic designator D6)
D6_C "SZMMSZ15ET1G" ONSC-SOD-123-2-425-04_V 10200,7325 r0 top (schematic designator D6)
D6_D "SZMMSZ15ET1G" ONSC-SOD-123-2-425-04_V 10200,10325 r0 top (schematic designator D6)
D7_A "1N4148WS" FAIR-SOD-323_V 9794.88,845 r0 top (schematic designator D7)
D7_B "1N4148WS" FAIR-SOD-323_V 9800,3850 r0 top (schematic designator D7)
D7_C "1N4148WS" FAIR-SOD-323_V 9805.12,6830 r0 top (schematic designator D7)
D7_D "1N4148WS" FAIR-SOD-323_V 9794.88,9831.61 r0 top (schematic designator D7)
D8_A "1N4148WS" FAIR-SOD-323_V 10780.12,750 r0 top (schematic designator D8)
D8_B "1N4148WS" FAIR-SOD-323_V 10780.12,3750.2 r0 top (schematic designator D8)
D8_C "1N4148WS" FAIR-SOD-323_V 10780.12,6750.2 r0 top (schematic designator D8)
D8_D "1N4148WS" FAIR-SOD-323_V 10779.09,9750 r0 top (schematic designator D8)
FB1 "BLM18SG121TN1D" FP-BLM18-0_15-t0_5-d1_2-IPC_B 6470,400 r0 top
FB2 "BLM18SG121TN1D" FP-BLM18-0_15-t0_5-d1_2-IPC_B 6470,11600 r0 top
J1 "M80-5000000M5-02-333-00-000" FP-M80-5000000M5-02-333-0-MFG 13815,11100 r90 top
J2 "ESQ-132-14-G-D" SMTC-ESQ-132-14-X-D 4000,11600 r180 top
J3 "ESQ-132-14-G-D" SMTC-ESQ-132-14-X-D 4000,300 r180 top
J4 "M80-5000000M5-02-333-00-000" FP-M80-5000000M5-02-333-0-MFG 13815,1100 r90 top
J5 "M80-5000000M5-02-333-00-000" FP-M80-5000000M5-02-333-0-MFG 13815,4100 r90 top
J6 "M80-5000000M5-02-333-00-000" FP-M80-5000000M5-02-333-0-MFG 13815,7100 r90 top
J7 "M80-5000000M5-02-333-00-000" FP-M80-5000000M5-02-333-0-MFG 13815,10100 r90 top
K1_A "G41C" G41C 12800,1500 r180 top (schematic designator K1)
K1_B "G41C" G41C 12800,4500 r180 top (schematic designator K1)
K1_C "G41C" G41C 12800,7500 r180 top (schematic designator K1)
K1_D "G41C" G41C 12800,10500 r180 top (schematic designator K1)
K2_A "G41C" G41C 11750,1500 r180 top (schematic designator K2)
K2_B "G41C" G41C 11750,4500 r180 top (schematic designator K2)
K2_C "G41C" G41C 11750,7500 r180 top (schematic designator K2)
K2_D "G41C" G41C 11750,10500 r180 top (schematic designator K2)
L1 "SRR4028-180Y" INDP4848X30M 2405.24,5331.34 r0 top
L2 "SRR4028-180Y" INDP4848X30M 1485,7040 r0 top
L4 "SRR4028-180Y" INDP4848X30M 1485,5935 r0 top
MH1 "MH-MARS2-6-32" "MH-M3-Footprint-1 - Oversized MARS2" 250,250 r0 top
MH2 "MH-MARS2-6-32" "MH-M3-Footprint-1 - Oversized MARS2" 250,4000 r0 top locked
MH3 "MH-MARS2-6-32" "MH-M3-Footprint-1 - Oversized MARS2" 250,8000 r0 top
MH4 "MH-MARS2-6-32" "MH-M3-Footprint-1 - Oversized MARS2" 250,11750 r0 top
MH5 "MH-MARS2-6-32" "MH-M3-Footprint-1 - Oversized MARS2" 4500,11750 r0 top
MH6 "MH-MARS2-6-32" "MH-M3-Footprint-1 - Oversized MARS2" 3500,6000 r0 top
MH7 "MH-MARS2-6-32" "MH-M3-Footprint-1 - Oversized MARS2" 4500,250 r0 top
MH8 "MH-MARS2-6-32" "MH-M3-Footprint-1 - Oversized MARS2" 6750,250 r0 top
MH9 "MH-MARS2-6-32" "MH-M3-Footprint-1 - Oversized MARS2" 6750,4000 r0 top
MH10 "MH-MARS2-6-32" "MH-M3-Footprint-1 - Oversized MARS2" 6750,8000 r0 top
MH11 "MH-MARS2-6-32" "MH-M3-Footprint-1 - Oversized MARS2" 6750,11750 r0 top
MH13 "MH-MARS2-6-32" "MH-M3-Footprint-1 - Oversized MARS2" 12275,2450 r0 top
MH14 "MH-MARS2-6-32" "MH-M3-Footprint-1 - Oversized MARS2" 12275,1700 r0 top
MH15 "MH-MARS2-6-32" "MH-M3-Footprint-1 - Oversized MARS2" 12275,5450 r0 top
MH16 "MH-MARS2-6-32" "MH-M3-Footprint-1 - Oversized MARS2" 12275,4700 r0 top
MH17 "MH-MARS2-6-32" "MH-M3-Footprint-1 - Oversized MARS2" 13750,250 r0 top
MH18 "MH-MARS2-6-32" "MH-M3-Footprint-1 - Oversized MARS2" 13750,3000 r0 top
MH19 "MH-MARS2-6-32" "MH-M3-Footprint-1 - Oversized MARS2" 13750,6000 r0 top
MH20 "MH-MARS2-6-32" "MH-M3-Footprint-1 - Oversized MARS2" 13750,9000 r0 top
MH21 "MH-MARS2-6-32" "MH-M3-Footprint-1 - Oversized MARS2" 13750,11750 r0 top
MH23 "MH-MARS2-6-32" "MH-M3-Footprint-1 - Oversized MARS2" 9000,7500 r0 top
MH25 "MH-MARS2-6-32" "MH-M3-Footprint-1 - Oversized MARS2" 9000,4500 r0 top
MH26 "MH-MARS2-6-32" "MH-M3-Footprint-1 - Oversized MARS2" 12275,10700 r0 top
MH27 "MH-MARS2-6-32" "MH-M3-Footprint-1 - Oversized MARS2" 12275,8450 r0 top
MH28 "MH-MARS2-6-32" "MH-M3-Footprint-1 - Oversized MARS2" 12275,7700 r0 top
MH29 "MH-MARS2-6-32" "MH-M3-Footprint-1 - Oversized MARS2" 12275,11450 r0 top
PS1_A "RS3-2412S" CONV_RS3-2412S 8275,2125 r0 top (schematic designator PS1)
PS1_B "RS3-2412S" CONV_RS3-2412S 8275.39,5119.88 r0 top (schematic designator PS1)
PS1_C "RS3-2412S" CONV_RS3-2412S 8275.39,8119.88 r0 top (schematic designator PS1)
PS1_D "RS3-2412S" CONV_RS3-2412S 8275.39,11119.88 r0 top (schematic designator PS1)
Q1 "SPD04P10PG" INF-PG-TO252-3-1_M 820.24,8441.02 r270 top
Q2_A "TN2504N-G" SOT89-150P341X160-3M 7169.72,2225 r270 top (schematic designator Q2)
Q2_B "TN2504N-G" SOT89-150P341X160-3M 7519.72,2225 r270 top (schematic designator Q2)
Q2_C "TN2504N-G" SOT89-150P341X160-3M 7169.72,5225 r270 top (schematic designator Q2)
Q2_D "TN2504N-G" SOT89-150P341X160-3M 7519.72,5225 r270 top (schematic designator Q2)
Q2_E "TN2504N-G" SOT89-150P341X160-3M 7169.72,8225 r270 top (schematic designator Q2)
Q2_F "TN2504N-G" SOT89-150P341X160-3M 7519.72,8225 r270 top (schematic designator Q2)
Q2_G "TN2504N-G" SOT89-150P341X160-3M 7165,11225 r270 top (schematic designator Q2)
Q2_H "TN2504N-G" SOT89-150P341X160-3M 7519.72,11225 r270 top (schematic designator Q2)
Q3_A "IXFN66N85X" IXFN66N85X-Footprint-1 10200,1950 r0 top (schematic designator Q3)
Q3_B "IXFN66N85X" IXFN66N85X-Footprint-1 10200,4950 r0 top (schematic designator Q3)
Q3_C "IXFN66N85X" IXFN66N85X-Footprint-1 10200,7950 r0 top (schematic designator Q3)
Q3_D "IXFN66N85X" IXFN66N85X-Footprint-1 10200,10950 r0 top (schematic designator Q3)
Q4_A "140357145100" WL-OCPT_SOP4 8225,1200 r0 top (schematic designator Q4)
Q4_B "140357145100" WL-OCPT_SOP4 8225,4275 r0 top (schematic designator Q4)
